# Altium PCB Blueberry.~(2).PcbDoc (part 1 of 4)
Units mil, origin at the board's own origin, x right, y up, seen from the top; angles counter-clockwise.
Board outline 2559.06 x 2204.72 mil, 6 copper layers (Top Layer, Mid-Layer 1, Mid-Layer 2, Mid-Layer 3, Mid-Layer 4, Bottom Layer); 211 components, 214 nets, 1171 pads, 598 vias.
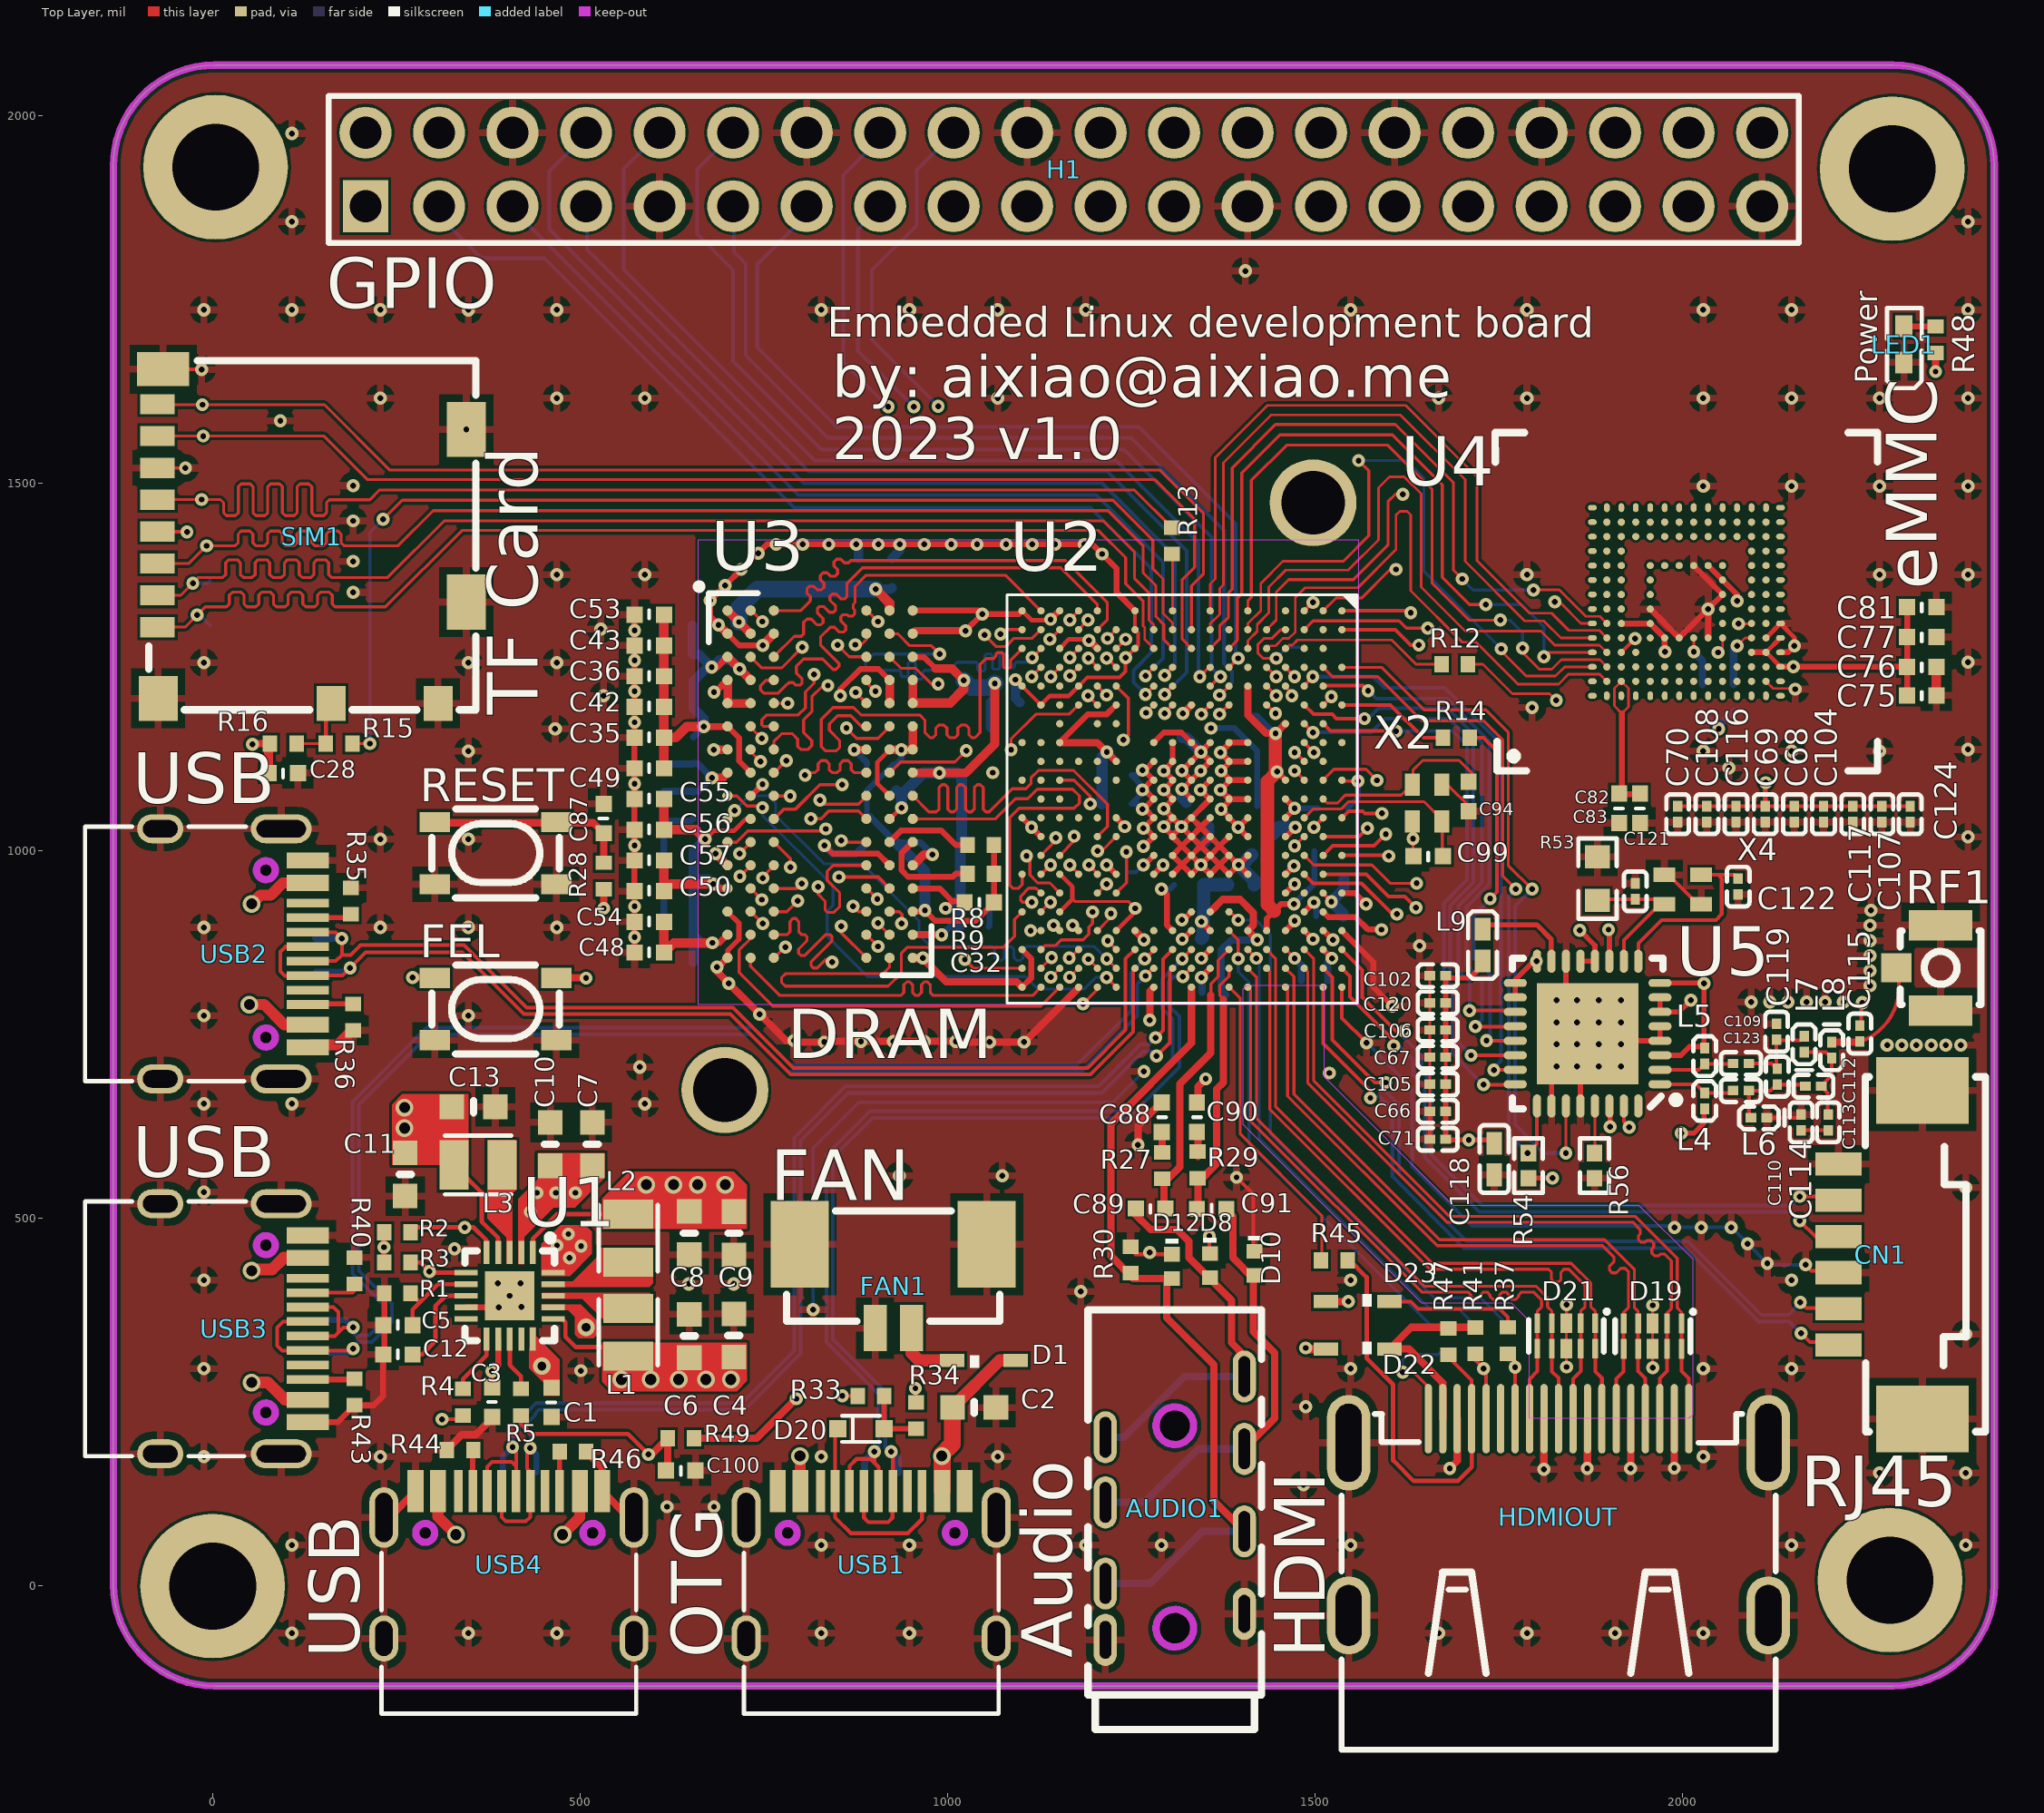
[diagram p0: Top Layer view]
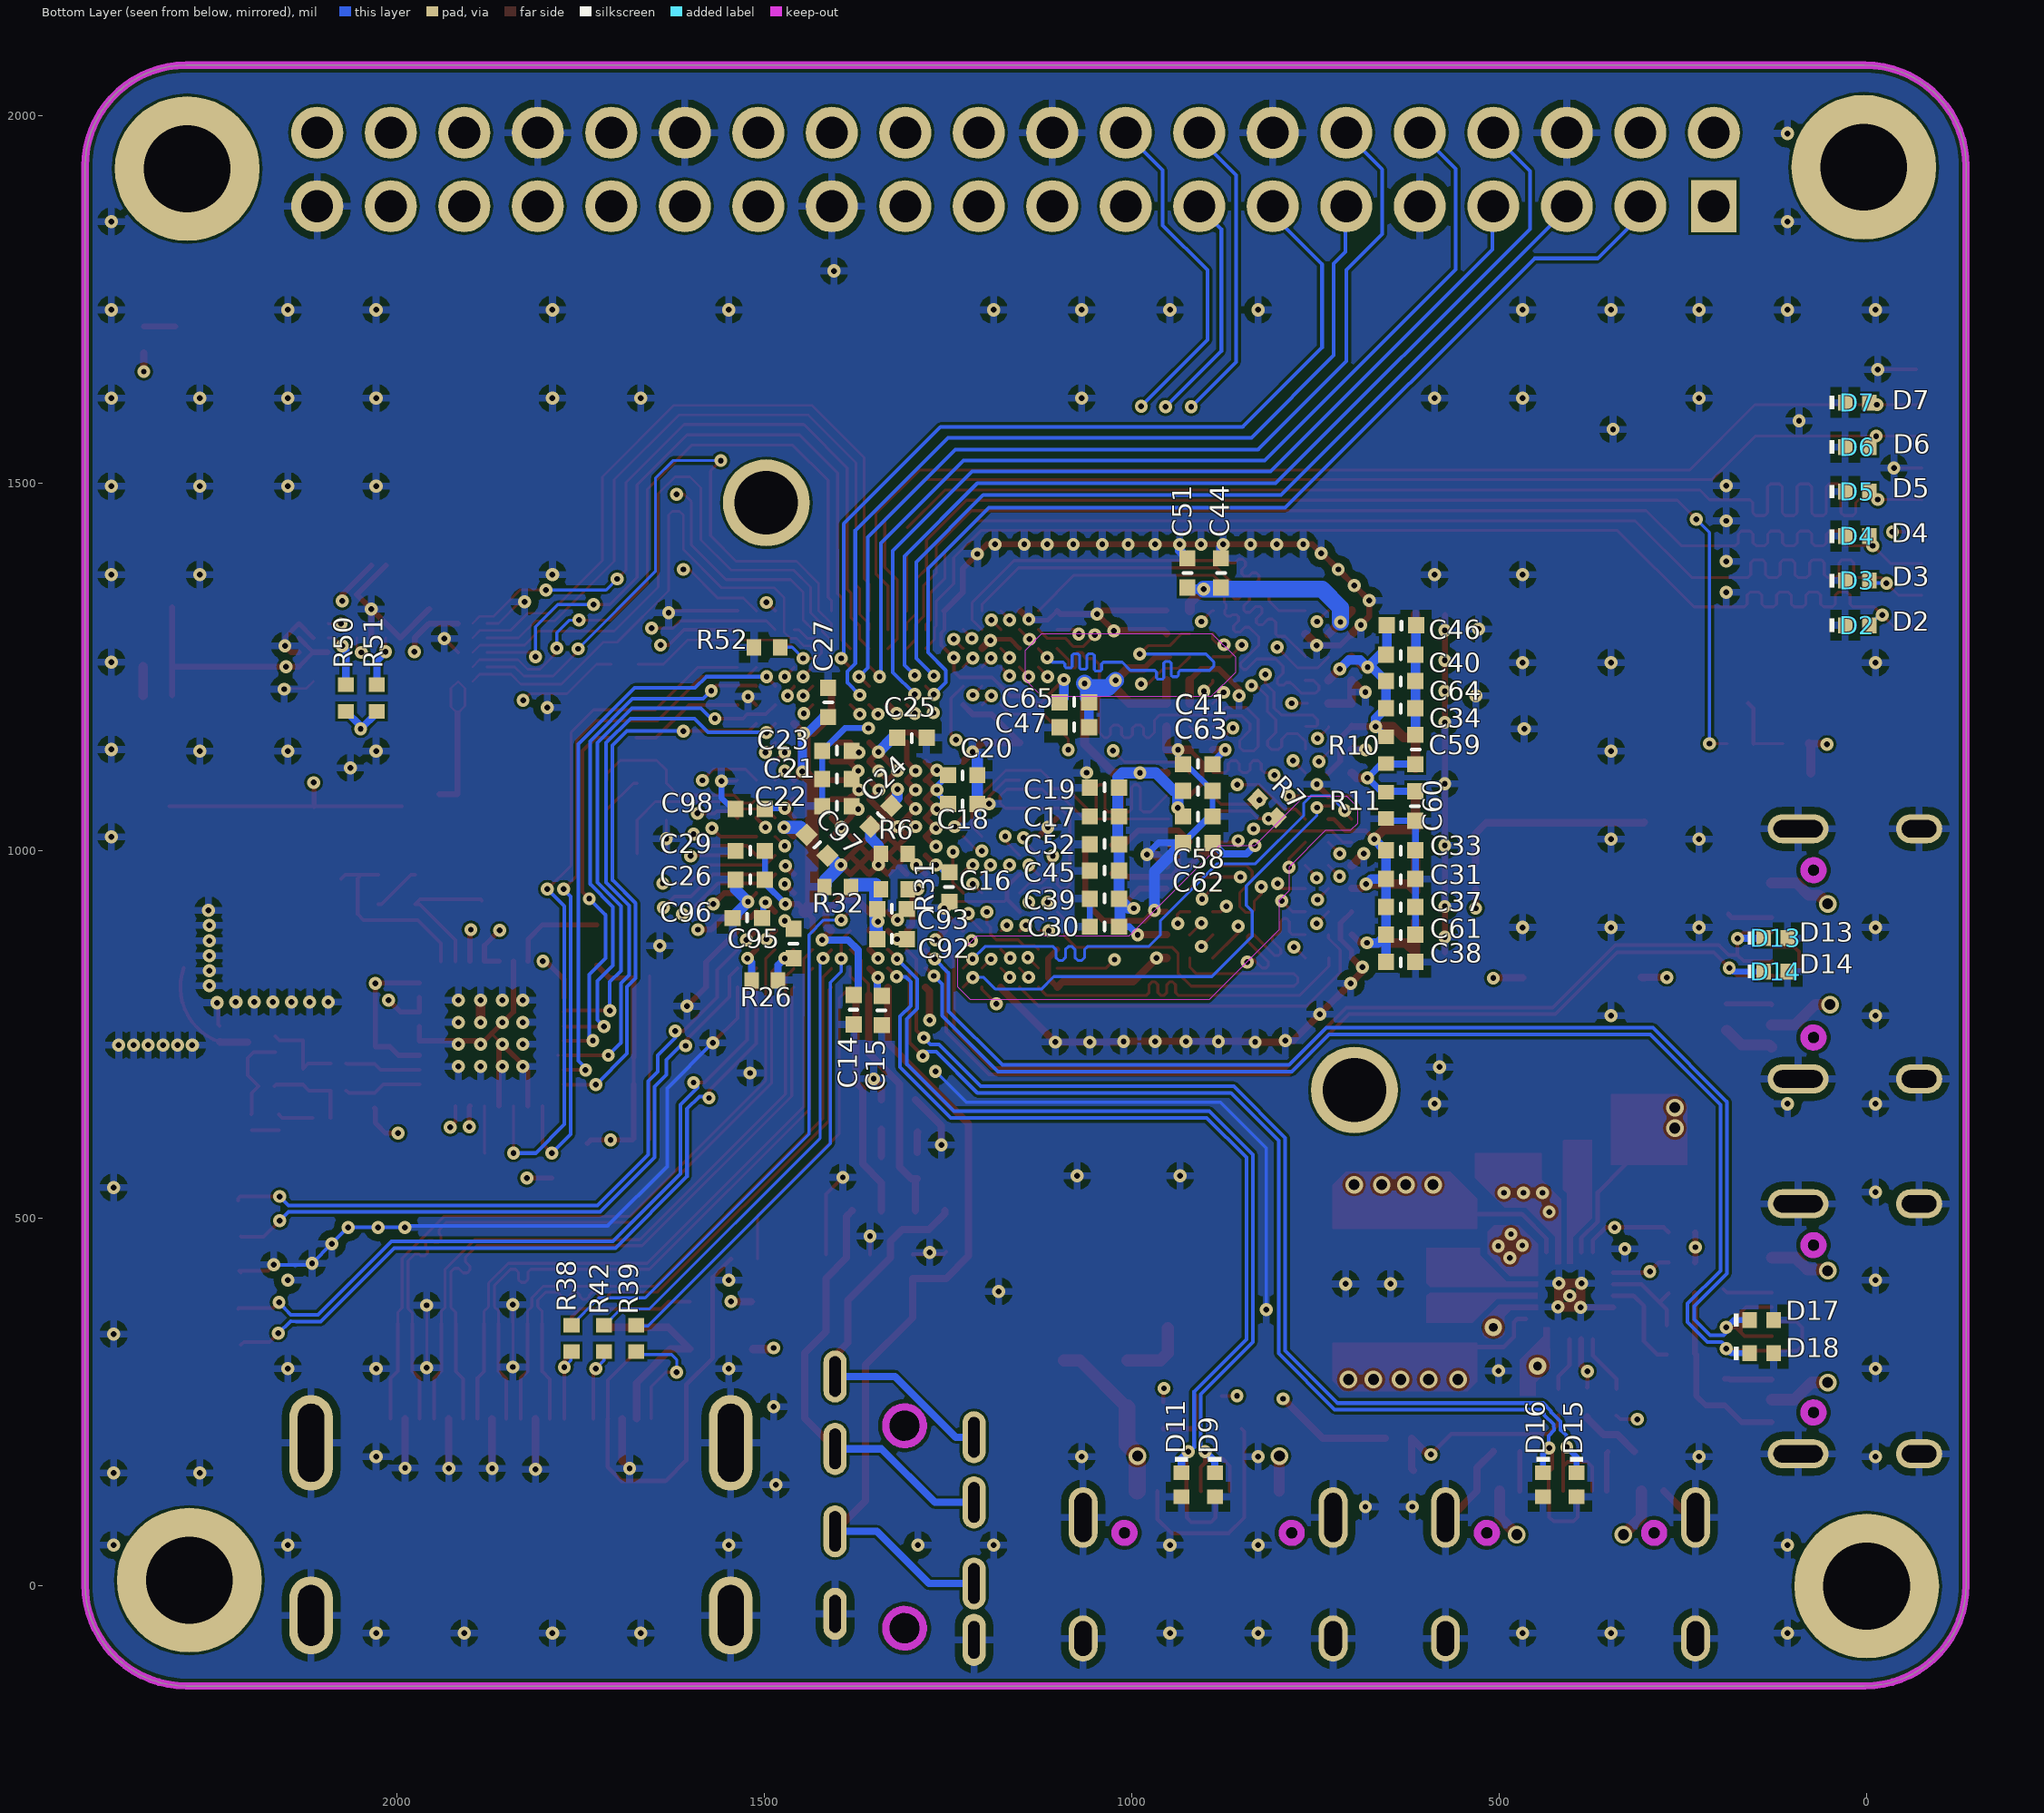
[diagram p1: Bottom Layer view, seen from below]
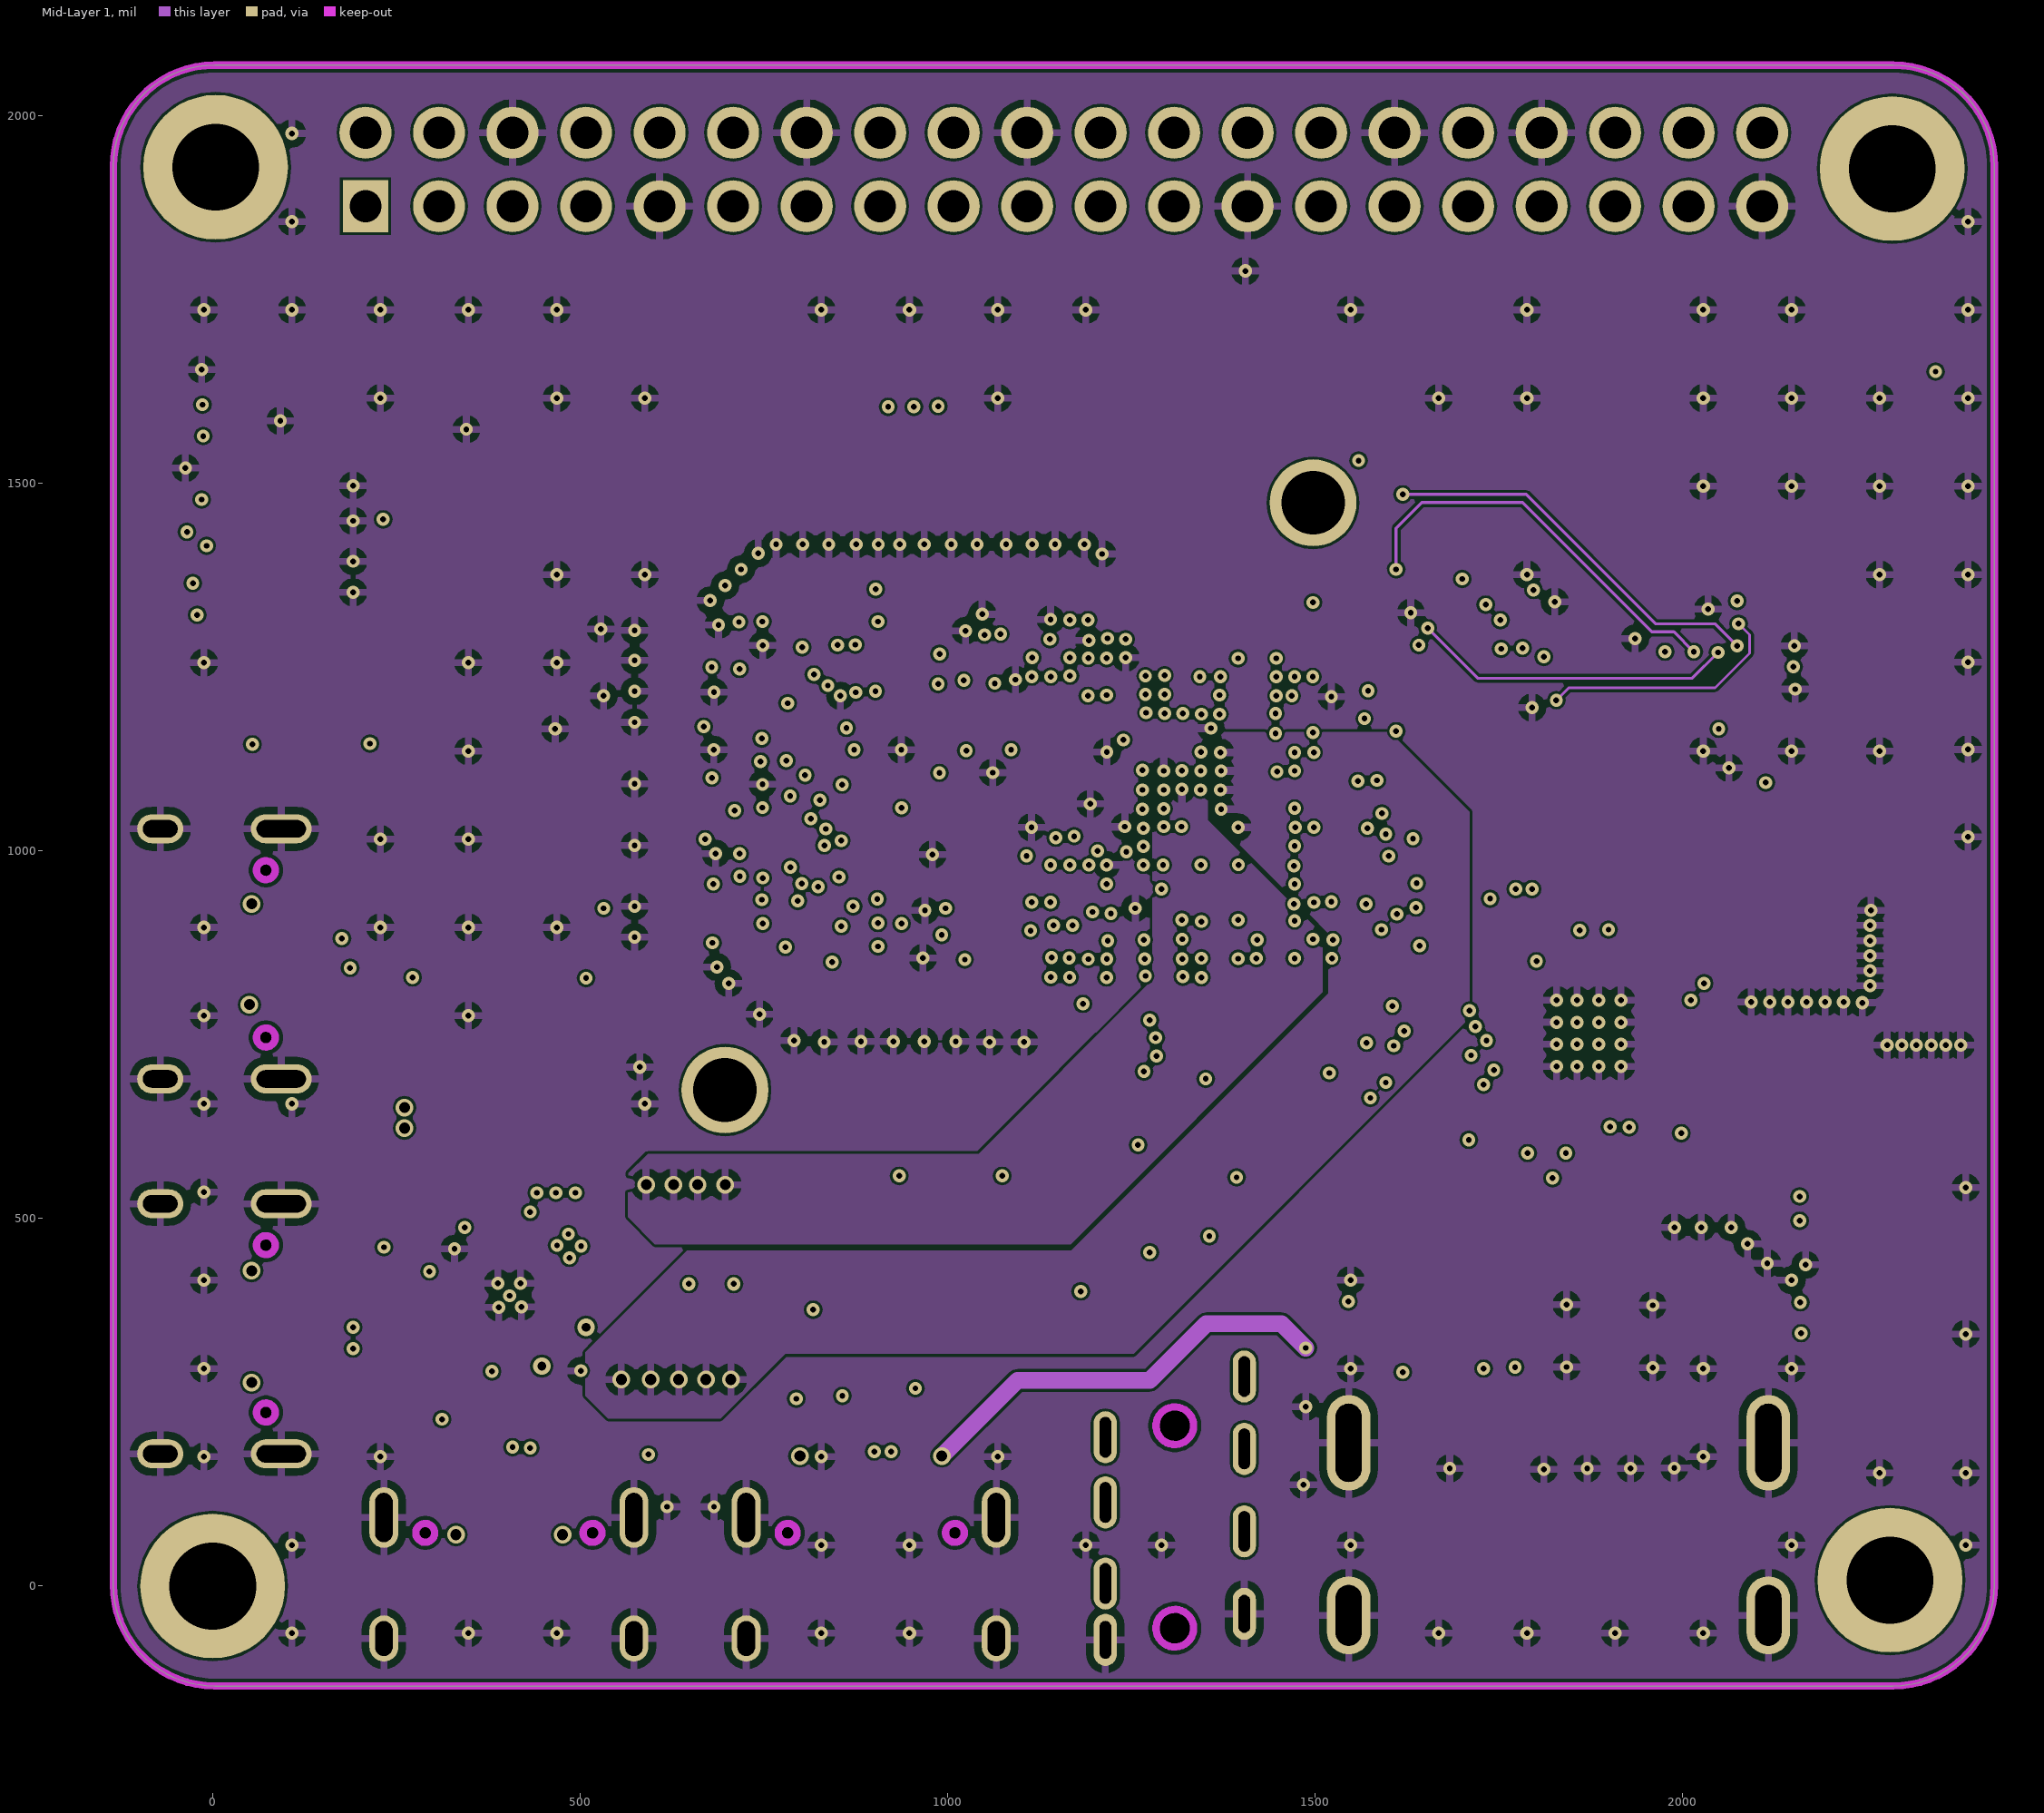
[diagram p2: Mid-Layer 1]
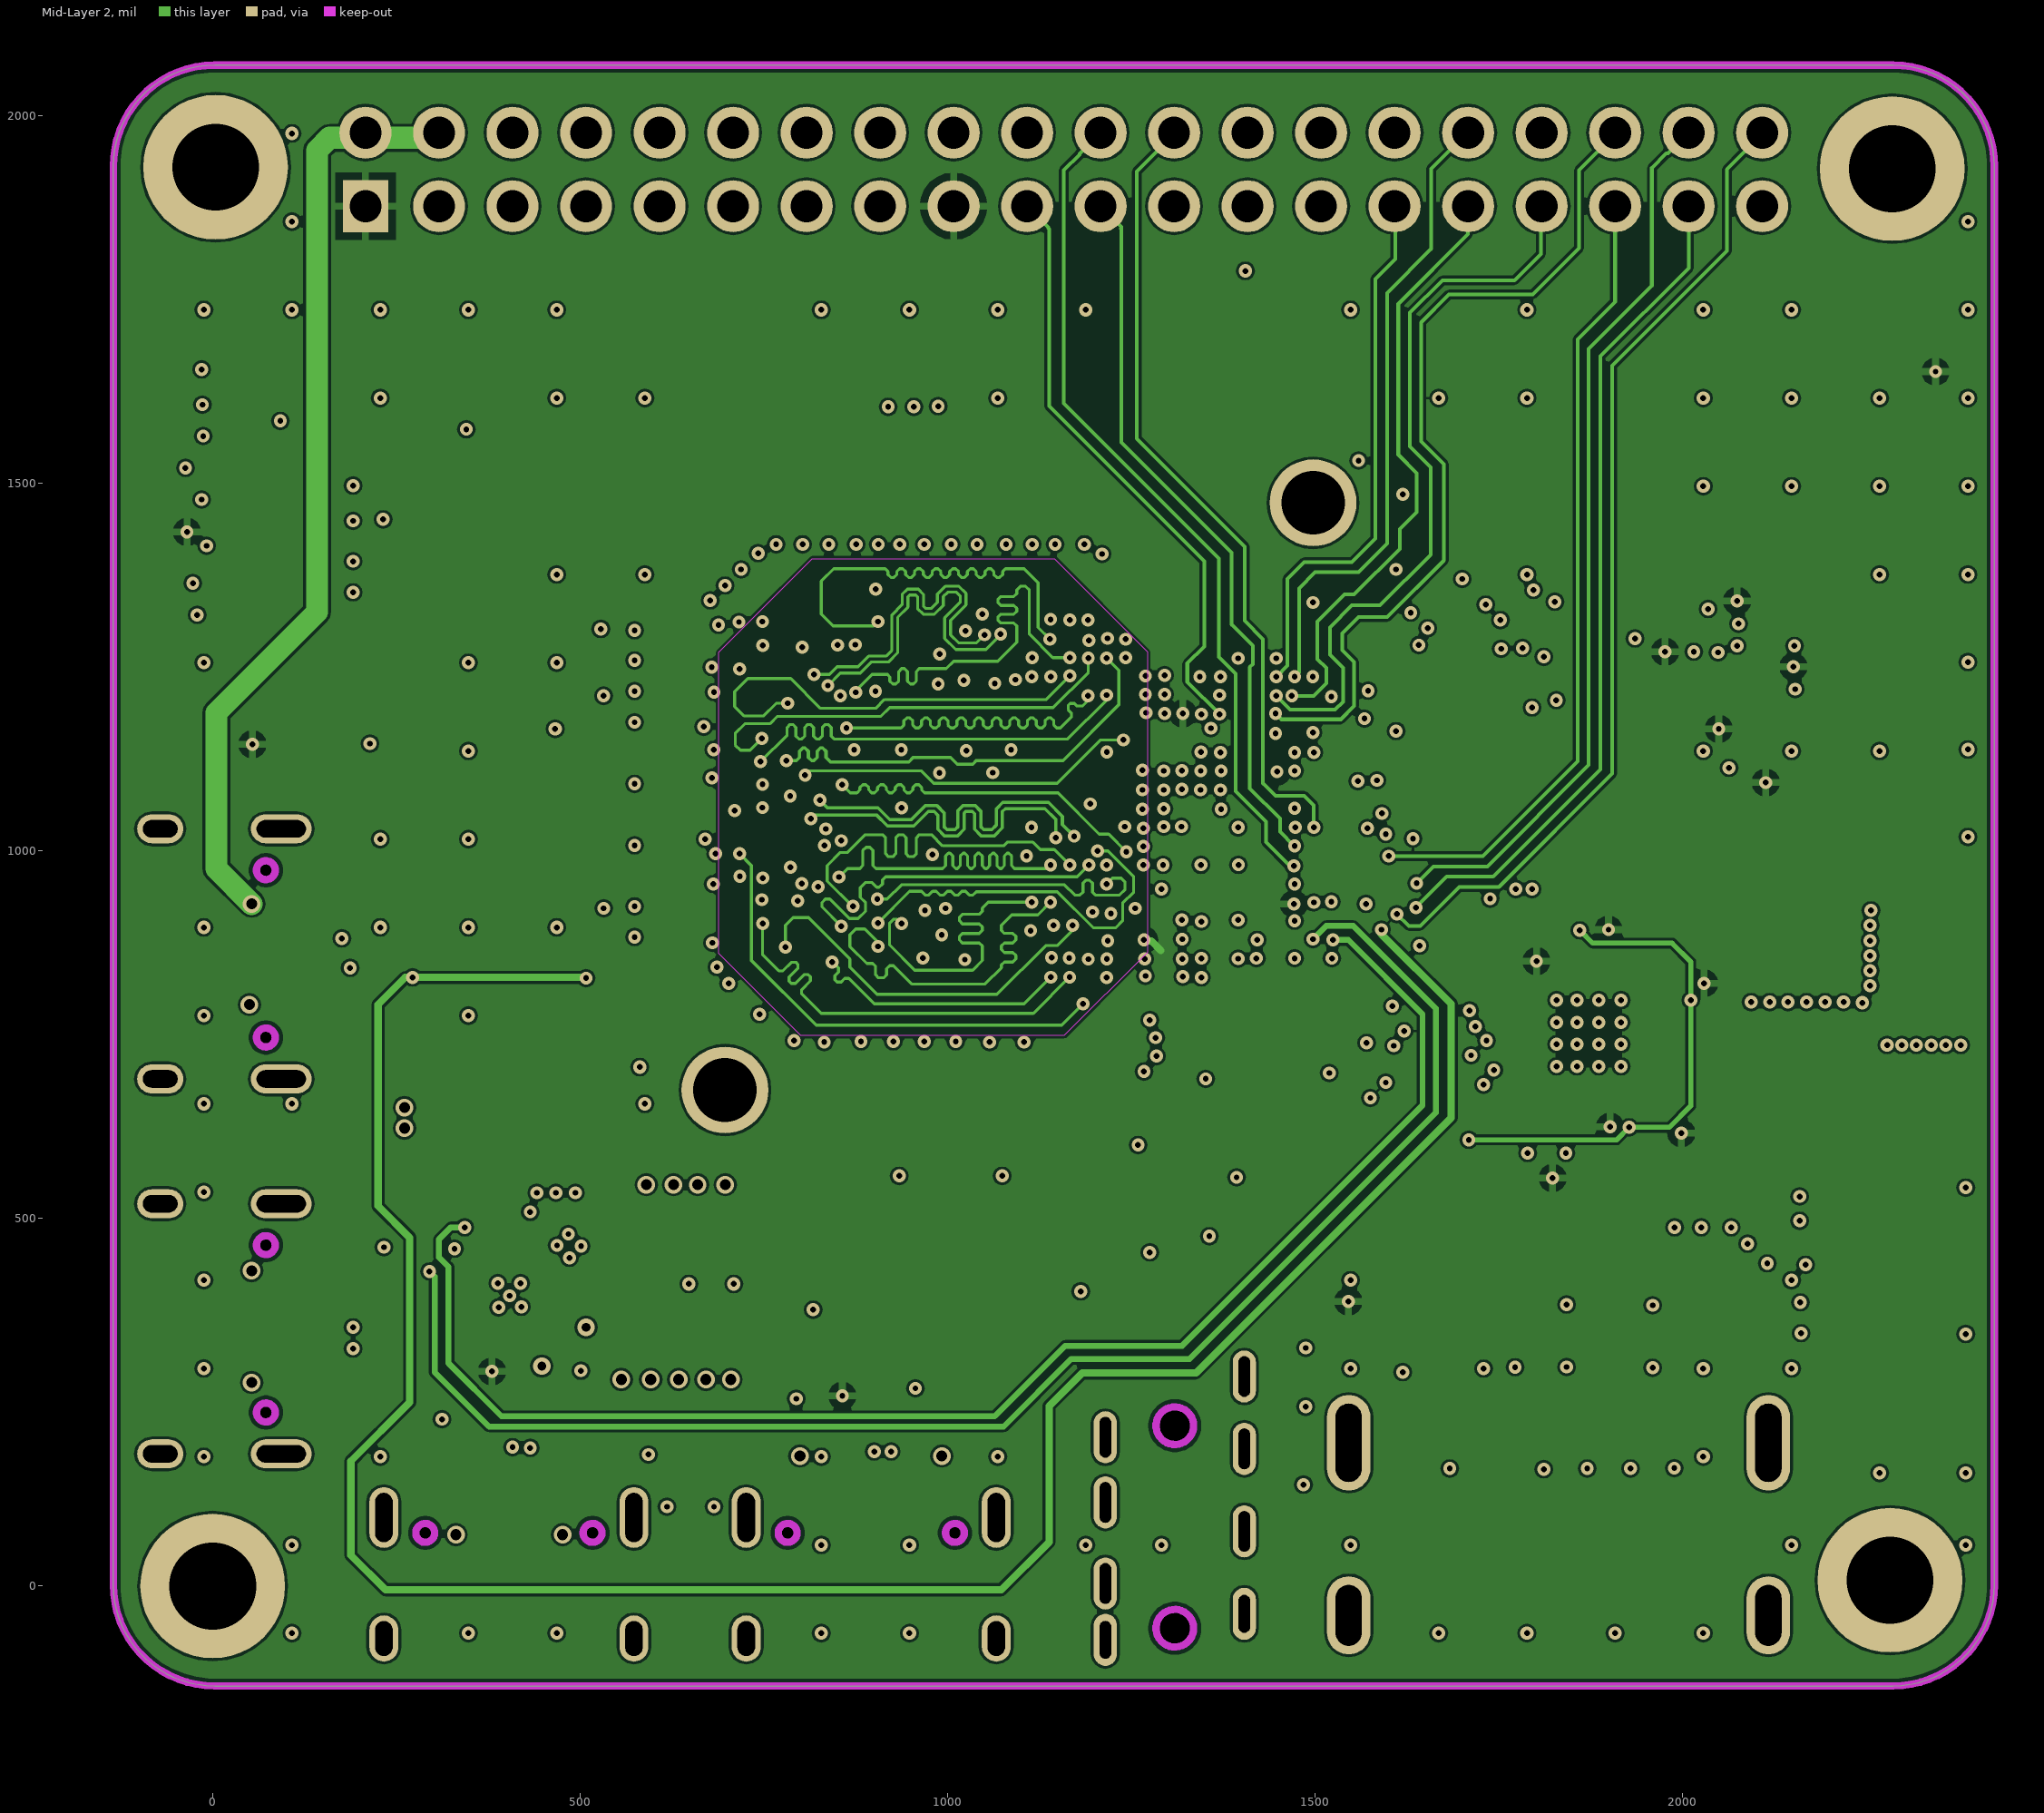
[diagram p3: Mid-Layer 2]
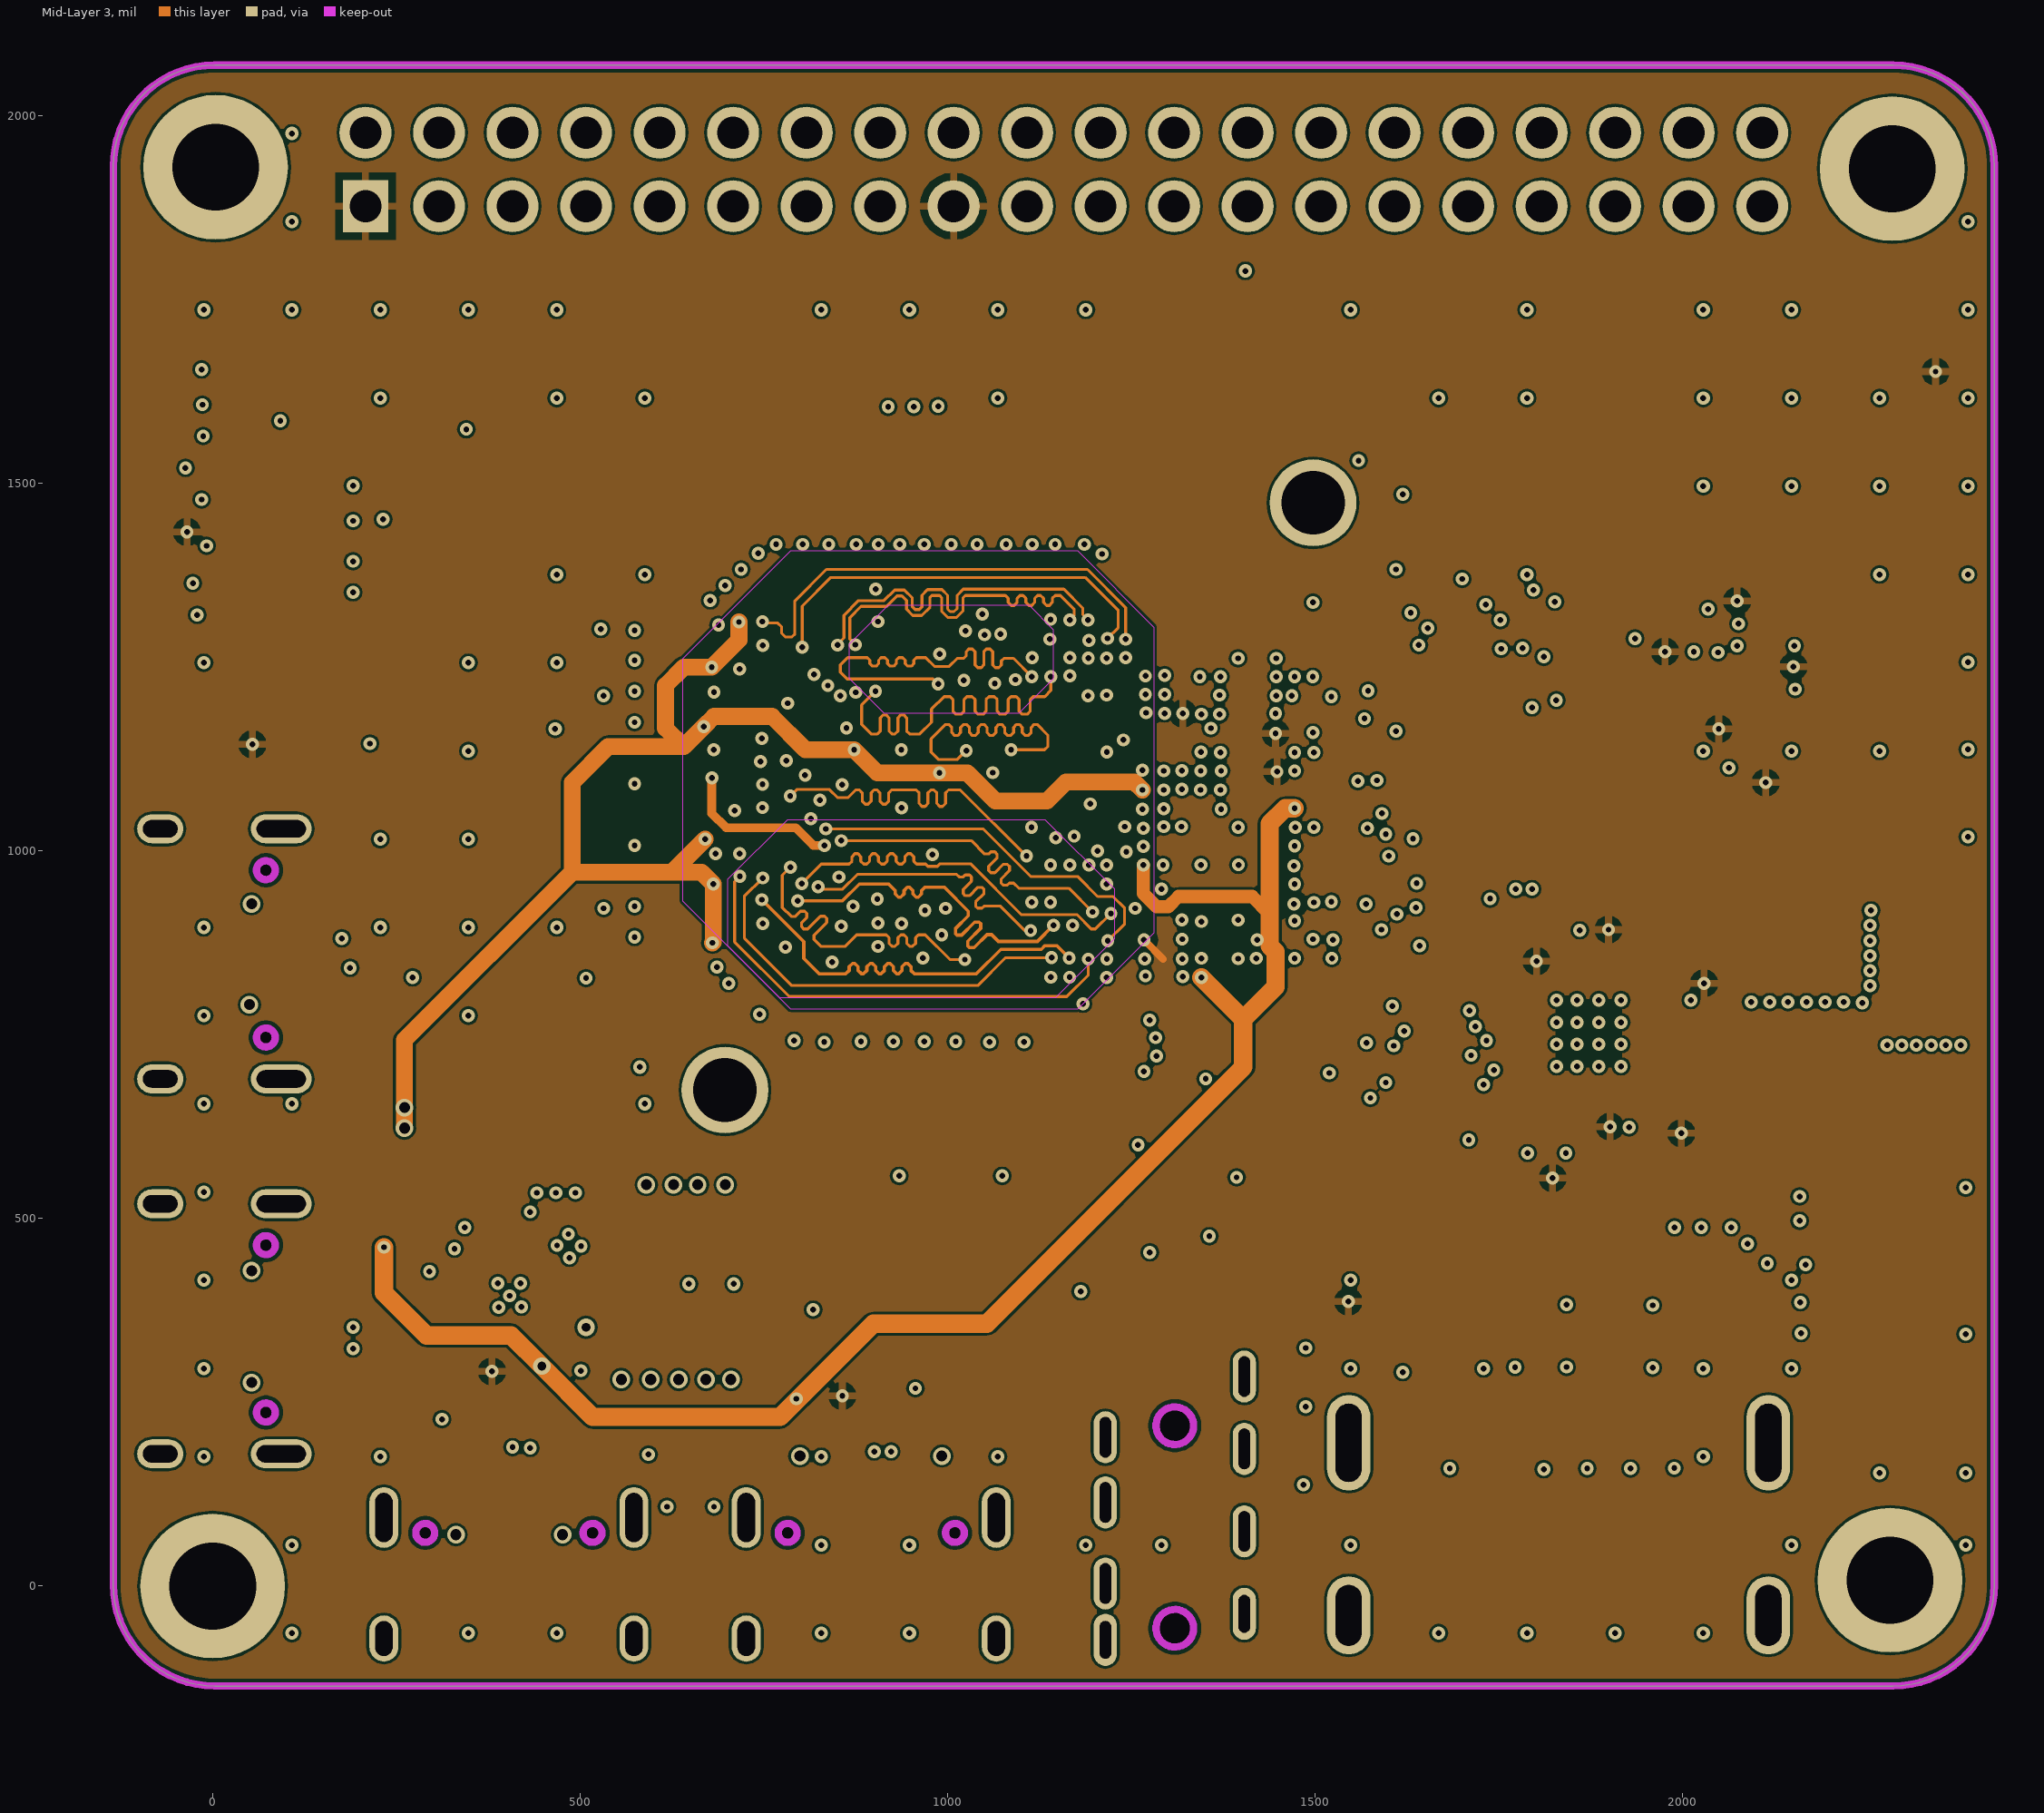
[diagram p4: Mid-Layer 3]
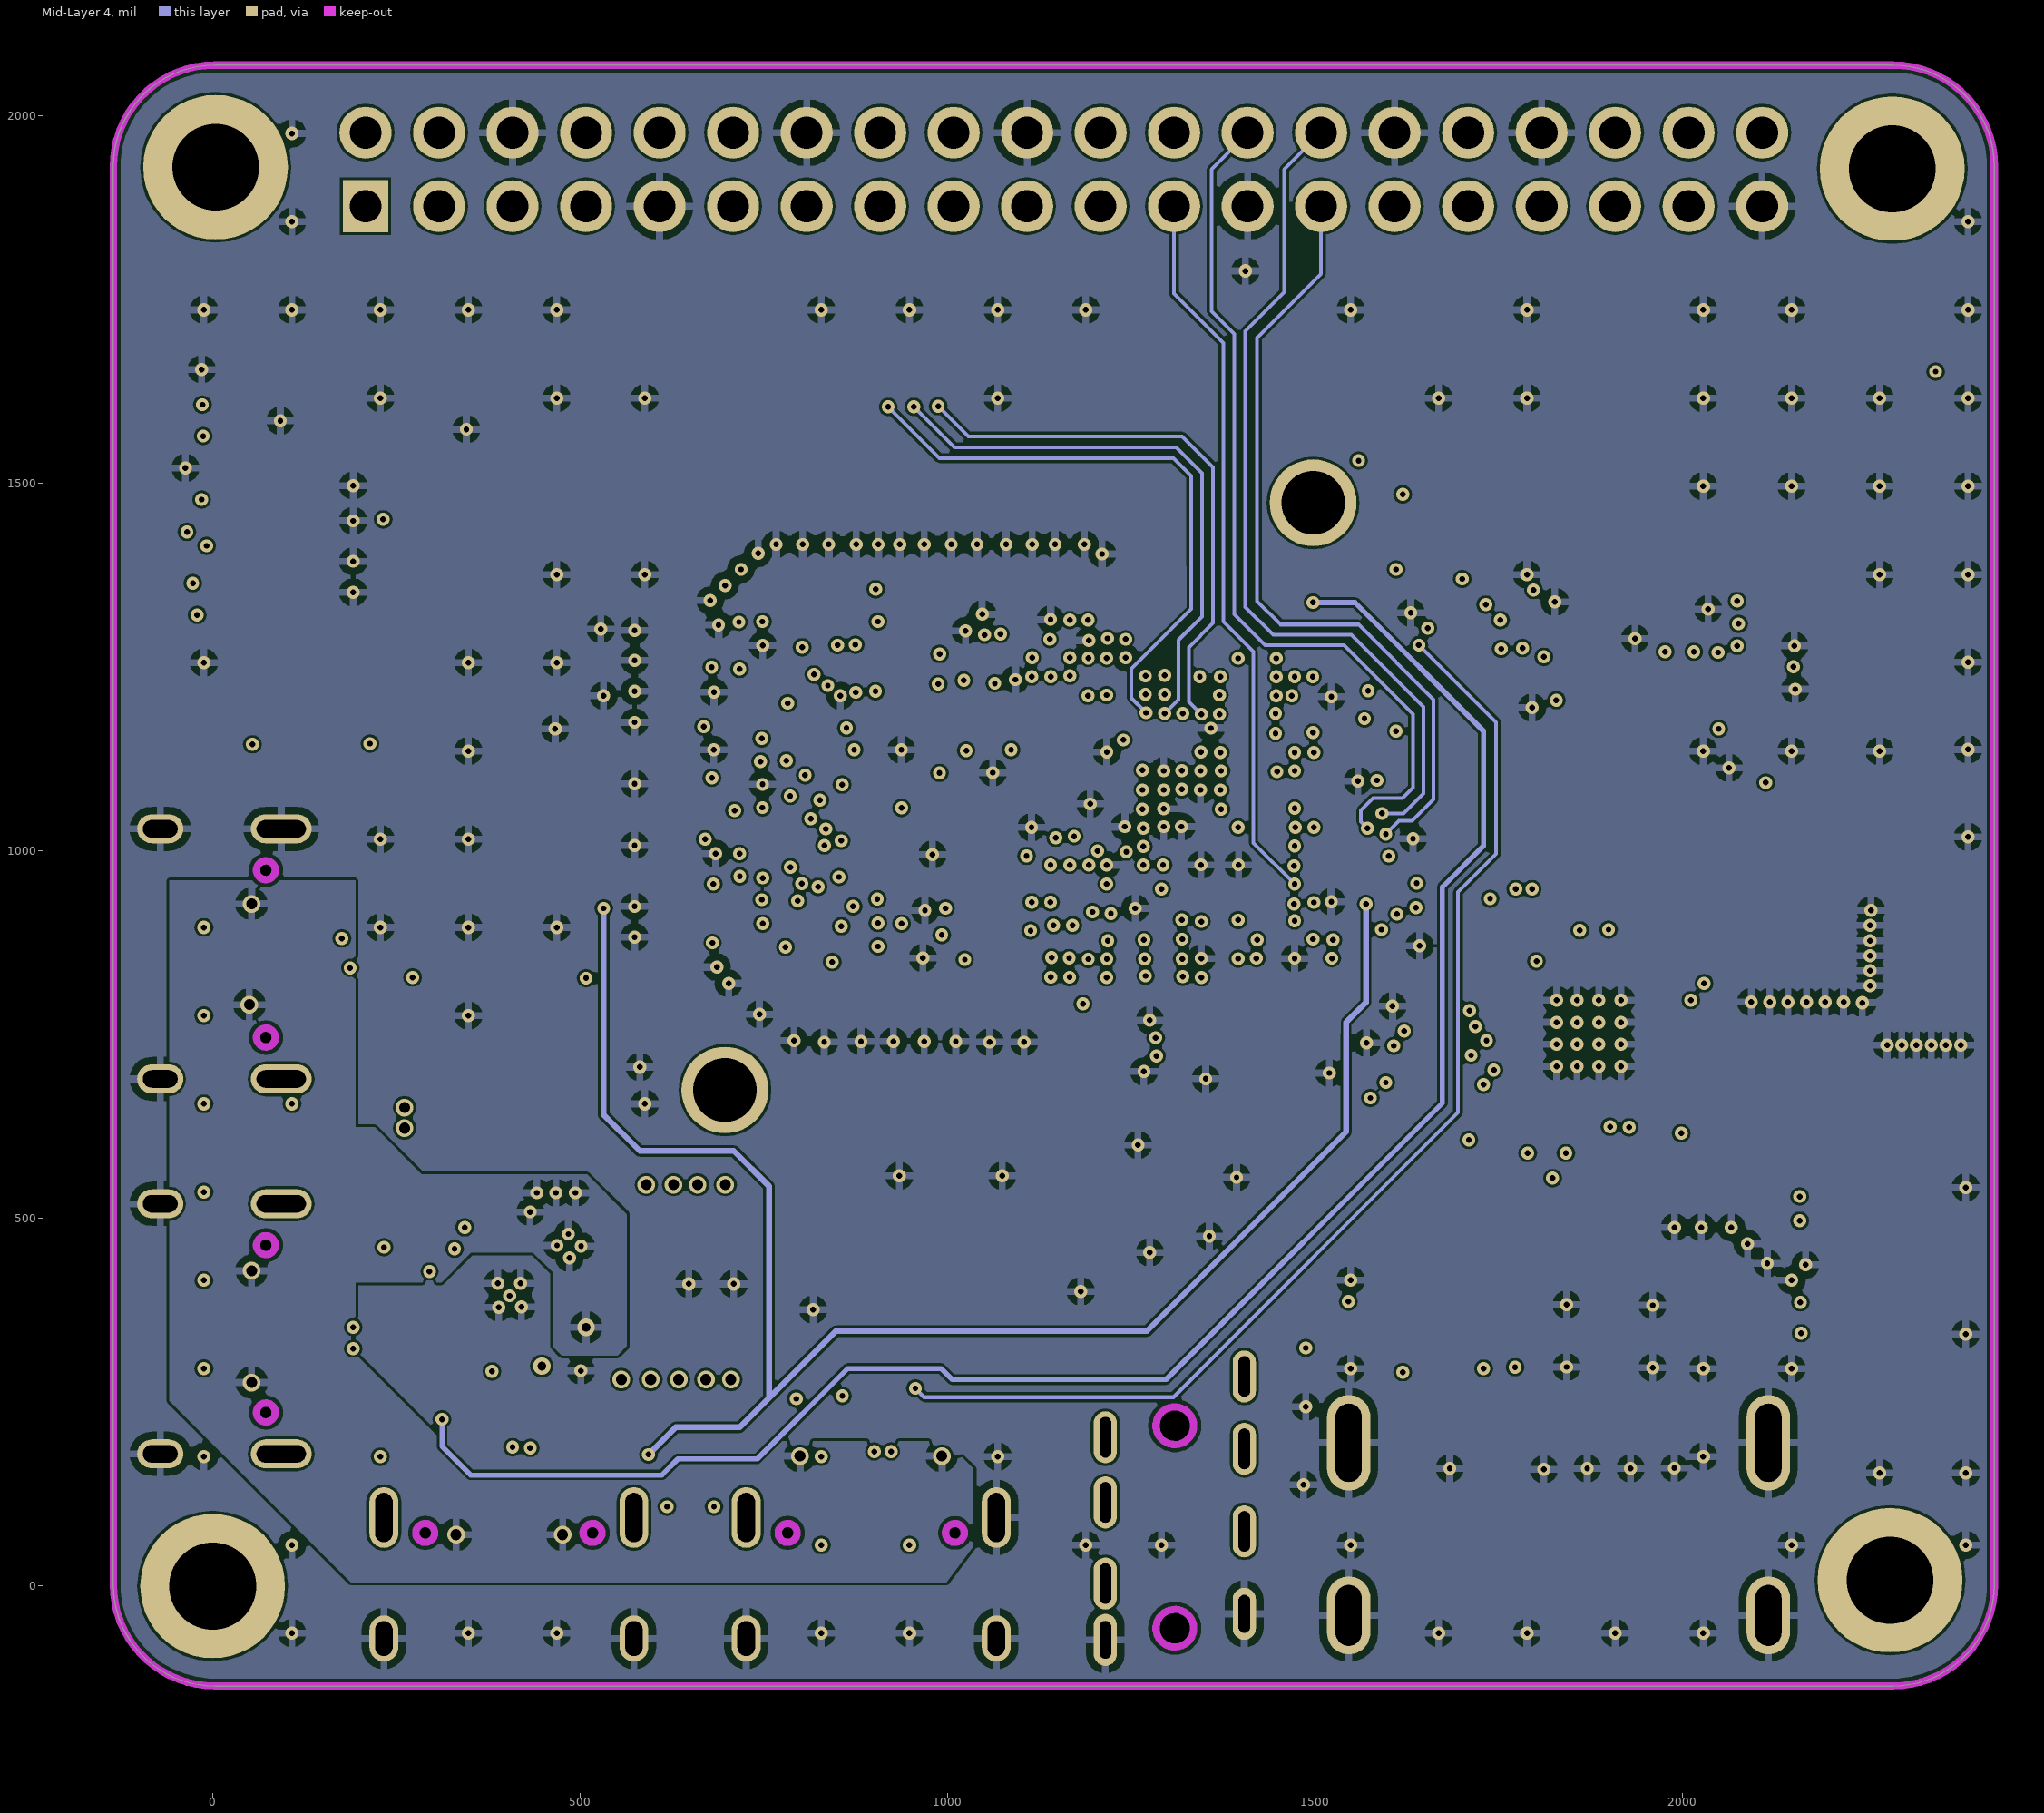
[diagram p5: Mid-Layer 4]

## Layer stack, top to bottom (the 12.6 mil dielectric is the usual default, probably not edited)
Top Solder: solder mask 0.4, Solder Resist, Dk 3.5
Top Layer: signal copper 1.4
Dielectric 1: dielectric 12.6, FR-4, Dk 4.8
Mid-Layer 1: signal copper 1.4
Dielectric4: dielectric 12.6, FR-4, Dk 4.8
Mid-Layer 2: signal copper 1.4
Dielectric3: dielectric 12.6, FR-4, Dk 4.8
Mid-Layer 3: signal copper 1.4
Dielectric2: dielectric 12.6, FR-4, Dk 4.8
Mid-Layer 4: signal copper 1.4
Dielectric5: dielectric 12.6, FR-4, Dk 4.8
Bottom Layer: signal copper 1.4
Bottom Solder: solder mask 0.4, Solder Resist, Dk 3.5

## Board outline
-135.17,1.96 ccw(c2.63,1.96) 2.63,-135.83 2286.09,-135.83 ccw(c2286.09,1.96) 2423.89,1.96 2423.89,1931.09 ccw(c2286.09,1931.09) 2286.09,2068.89 2.63,2068.89 ccw(c2.63,1931.09) -135.17,1931.09

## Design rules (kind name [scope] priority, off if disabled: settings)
BoardOutlineClearance [All] p1: gap=10 ignorepadtopadclearanceinfootprint=FALSE except(0: Arc-SplitContinuation Track-OutlineEdge Track-SplitContinuation SMDPad-SplitContinuation THPad-SplitContinuation Via-SplitContinuation Fill-SplitContinuation Poly-SplitContinuation Region-SplitContinuation Text-OutlineEdge Text-SplitContinuation; 3.5: Track-CutoutEdge SMDPad-OutlineEdge SMDPad-CutoutEdge THPad-OutlineEdge THPad-CutoutEdge Via-CutoutEdge Fill-CutoutEdge Region-CutoutEdge)
Clearance Via [All vs inpolygon] p1: gap=3.5 ignorepadtopadclearanceinfootprint=FALSE
Clearance [All] p2: gap=3.5 ignorepadtopadclearanceinfootprint=FALSE except(3: Arc-Arc; 7: Arc-Track Arc-SMDPad Arc-THPad Arc-Via Arc-Fill Arc-Poly Arc-Region Arc-Text Arc-Hole)
DiffPairsRouting [All] p1: maxlimit=10 minlimit=10 mostfreqgap=10 toplayer_minwidth=15 toplayer_maxwidth=15 toplayer_prefwidth=15 midlayer1_minwidth=15 midlayer1_maxwidth=15 midlayer1_prefwidth=15 midlayer2_minwidth=15 midlayer2_maxwidth=15 midlayer2_prefwidth=15 midlayer3_minwidth=15 midlayer3_maxwidth=15 midlayer3_prefwidth=15 midlayer4_minwidth=15 midlayer4_maxwidth=15 midlayer4_prefwidth=15 bottomlayer_minwidth=15 bottomlayer_maxwidth=15 bottomlayer_prefwidth=15 maxuncoupledlength=500
HoleSize [All] p1: absolutevalues=TRUE maxlimit=150 minlimit=1 maxpercent=80.000 minpercent=20.000
HoleToHoleClearance [All] p1: gap=0 allowstackedmicrovias=TRUE
MinimumSolderMaskSliver [All] p1: minsoldermaskwidth=0
PolygonConnect DRAMCopper [All] p1: connectstyle=Relief reliefconductorwidth=10 reliefentries=4 polygonreliefangle="90 Angle" airgapwidth=10
PolygonConnect TBCopper [All] p2: connectstyle=Relief reliefconductorwidth=4 reliefentries=4 polygonreliefangle="90 Angle" airgapwidth=4
PolygonConnect [All] p3: connectstyle=Relief reliefconductorwidth=10 reliefentries=4 polygonreliefangle="90 Angle" airgapwidth=10
RoutingVias [All] p1: holewidth=7.9 width=17.7 viastyle="Through Hole" minholewidth=7.9 minwidth=17.7 maxholewidth=28 maxwidth=50
SilkToSilkClearance [All] p1: silktosilkclearance=0
SilkToSolderMaskClearance [IsPad] p1: minsilkscreentomaskgap=0 clearancetoexposedcopper=TRUE
SolderMaskExpansion [All] p1: expansion=4 istentingtop=FALSE
SupplyNets "Schematic Supply Nets_7" [InNet('H5V')] p1: voltage=0.000
SupplyNets "Schematic Supply Nets_6" [InNet('VDD_CPU')] p2: voltage=0.000
SupplyNets "Schematic Supply Nets_5" [InNet('VCC_DRAM')] p3: voltage=0.000
SupplyNets "Schematic Supply Nets_4" [InNet('VDD_GPU')] p4: voltage=0.000
SupplyNets "Schematic Supply Nets_3" [InNet('VDD33')] p5: voltage=0.000
SupplyNets "Schematic Supply Nets_2" [InNet('GND')] p6: voltage=0.000
SupplyNets "Schematic Supply Nets_1" [InNet('1V8')] p7: voltage=0.000
SupplyNets "Schematic Supply Nets" [InNet('VBUS')] p8: voltage=0.000
Width [All] p1: maxlimit=100 minlimit=3 preferedwidth=4
24 further rules are at their usual default settings.

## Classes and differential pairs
component class POWER: C1 C2 C3 C4 C5 C6 C7 C8 C9 C10 C11 C12 C13 C14 C15 C16 C17 C18 C19 C20 C21 C22 C23 C24 C25 C26 C27 C28 C29 C100 D1 FAN1 L1 L2 L3 LED1 R1 R2 R3 R4 R5 R48 R49 U1
component class PLL-IO: AUDIO1 C87 C88 C89 C90 C91 C92 C93 C94 C95 C96 C97 C98 C99 CN1 D8 D9 D10 D11 D12 D13 D14 D15 D16 D17 D18 D19 D20 D21 D22 D23 FEL HDMIOUT R26 R27 R28 R29 R30 R31 R32 R33 R34 R35 R36 R37 R38 R39 R40 R41 R42 R43 R44 R45 R46 R47 RESET USB1 USB2 USB3 USB4 X2
component class IO: C66 C67 C68 C69 C70 C71 C75 C76 C77 C81 C82 C83 C102 C104 C105 C106 C107 C108 C109 C110 C112 C113 C114 C115 C116 C117 C118 C119 C120 C121 C122 C123 C124 D2 D3 D4 D5 D6 D7 H1 L4 L5 L6 L7 L8 L9 R12 R13 R14 R15 R16 R50 R51 R52 R53 R54 R56 RF1 SIM1 U4 U5 X4
component class DRAM: C30 C31 C32 C33 C34 C35 C36 C37 C38 C39 C40 C41 C42 C43 C44 C45 C46 C47 C48 C49 C50 C51 C52 C53 C54 C55 C56 C57 C58 C59 C60 C61 C62 C63 C64 C65 R6 R7 R8 R9 R10 R11 U2 U3
differential pair SDQS0: +SDQS0_P -SDQS0_N
differential pair EPHY_RX: +EPHY_RX_P -EPHY_RX_N
differential pair EPHY_TX: +EPHY_TX_P -EPHY_TX_N
differential pair D0: +D0_P -D0_N
differential pair D3: +D3_P -D3_N
differential pair D2: +D2_P -D2_N
differential pair HDMI_2: +HDMI_2_P -HDMI_2_N
differential pair HDMI_1: +HDMI_1_P -HDMI_1_N
differential pair HDMI_0: +HDMI_0_P -HDMI_0_N
differential pair HDMI_C: +HDMI_C_P -HDMI_C_N
differential pair D1: +D1_P -D1_N
differential pair SCK: +SCK_P -SCK_N
differential pair SDQS1: +SDQS1_P -SDQS1_N

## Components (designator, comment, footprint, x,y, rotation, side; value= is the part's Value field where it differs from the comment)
AUDIO1 "PJ-3930-8A" AUDIO-TH_PJ-3930-8A 1309,106 r180 top
C1 "CAP_0402" C0402-NSK 461,250 r90 top value=4.7uf
C2 "CAP_0603" "C0603 NSK" 1036,243 r0 top value=4.7uf
C3 "CAP_0402" C0402-NSK 380.44,250.27 r90 top value=4.7uf
C4 "CAP_0603" "C0603 NSK" 709.12,340.92 r90 top value=22uf
C5 "CAP_0402" C0402-NSK 252,355 r0 top value=4.7uf
C6 "CAP_0603" "C0603 NSK" 648.44,340.27 r90 top value=22uf
C7 "CAP_0603" "C0603 NSK" 516.44,601.27 r90 top value=4.7uf
C8 "CAP_0603" "C0603 NSK" 648.44,480.27 r270 top value=22uf
C9 "CAP_0603" "C0603 NSK" 709.12,479.92 r270 top value=22uf
C10 "CAP_0603" "C0603 NSK" 459.44,601.27 r90 top value=4.7uf
C11 "CAP_0603" "C0603 NSK" 262,560 r270 top value=22uf
C12 "CAP_0402" C0402-NSK 252,315 r0 top value=1uf
C13 "CAP_0603" "C0603 NSK" 355,652 r0 top value=22uf
C14 "CAP_0402" C0402-NSK 1378,784 r90 bottom value=100nF
C15 "CAP_0402" C0402-NSK 1340,783 r90 bottom value=100nF
C16 "CAP_0402" C0402-NSK 1248,951 r90 bottom value=100nF
C17 "CAP_0402" C0402-NSK 1036.97,1047.01 r180 bottom value=100nF
C18 "CAP_0402" C0402-NSK 1229.97,1064.01 r0 bottom value=100nF
C19 "CAP_0402" C0402-NSK 1037.03,1085.96 r180 bottom value=100nF
C20 "CAP_0402" C0402-NSK 1229.97,1103.01 r0 bottom value=100nF
C21 "CAP_0402" C0402-NSK 1401,1098 r180 bottom value=100nF
C22 "CAP_0402" C0402-NSK 1401,1061 r180 bottom value=100nF
C23 "CAP_0402" C0402-NSK 1401,1136 r180 bottom value=100nF
C24 "CAP_0402" C0402-NSK 1341,1047 r135 bottom value=100nF
C25 "CAP_0402" C0402-NSK 1299,1154 r0 bottom value=100nF
C26 "CAP_0402" C0402-NSK 1519,961 r180 bottom value=100nF
C27 "CAP_0402" C0402-NSK 1413,1202 r270 bottom value=100nF
C28 "CAP_0402" C0402-NSK 96.01,1106 r180 top value=100nF
C29 "CAP_0402" C0402-NSK 1519,1000 r180 bottom value=100nF
C30 "CAP_0402" C0402-NSK 1037,897 r180 bottom value=100nF
C31 "CAP_0402" C0402-NSK 634,962 r0 bottom value=100nF
C32 "CAP_0402" C0402-NSK 1043,930 r180 top value=100nF
C33 "CAP_0402" C0402-NSK 634,1001 r0 bottom value=100nF
C34 "CAP_0402" C0402-NSK 634,1194 r0 bottom value=100nF
C35 "CAP_0402" C0402-NSK 594,1154.15 r0 top value=100nF
C36 "CAP_0402" C0402-NSK 594,1237.69 r0 top value=100nF
C37 "CAP_0402" C0402-NSK 634,924 r0 bottom value=100nF
C38 "CAP_0402" C0402-NSK 634,849 r0 bottom value=100nF
C39 "CAP_0402" C0402-NSK 1037,935 r180 bottom value=100nF
C40 "CAP_0402" C0402-NSK 633.99,1267 r0 bottom value=100nF
C41 "CAP_0402" C0402-NSK 910,1118 r180 bottom value=100nF
C42 "CAP_0402" C0402-NSK 594,1195.92 r0 top value=100nF
C43 "CAP_0402" C0402-NSK 594,1279.46 r0 top value=100nF
C44 "CAP_0402" C0402-NSK 878.58,1378.16 r270 bottom value=100nF
C45 "CAP_0402" C0402-NSK 1037,973 r180 bottom value=100nF
C46 "CAP_0402" C0402-NSK 632.99,1307 r0 bottom value=100nF
C47 "CAP_0402" C0402-NSK 1078,1168 r180 bottom value=100nF
C48 "CAP_0402" C0402-NSK 594,861.77 r0 top value=100nF
C49 "CAP_0402" C0402-NSK 594,1112.38 r0 top value=100nF
C50 "CAP_0402" C0402-NSK 594,945.31 r0 top value=100nF
C51 "CAP_0402" C0402-NSK 924.27,1378.16 r270 bottom value=100nF
C52 "CAP_0402" C0402-NSK 1037,1009 r180 bottom value=100nF
C53 "CAP_0402" C0402-NSK 594,1321.23 r0 top value=100nF
C54 "CAP_0402" C0402-NSK 594,903.54 r0 top value=100nF
C55 "CAP_0402" C0402-NSK 594,1070.62 r0 top value=100nF
C56 "CAP_0402" C0402-NSK 594,1028.85 r0 top value=100nF
C57 "CAP_0402" C0402-NSK 594,987.08 r0 top value=100nF
C58 "CAP_0402" C0402-NSK 910,1011 r180 bottom value=100nF
C59 "CAP_0402" C0402-NSK 614,1138 r270 bottom value=100nF
C60 "CAP_0402" C0402-NSK 614,1061 r90 bottom value=100nF
C61 "CAP_0402" C0402-NSK 633.99,886 r0 bottom value=100nF
C62 "CAP_0402" C0402-NSK 910,1047 r0 bottom value=100nF
C63 "CAP_0402" C0402-NSK 910,1082 r0 bottom value=100nF
C64 "CAP_0402" C0402-NSK 634,1231 r0 bottom value=100nF
C65 "CAP_0402" C0402-NSK 1078,1202 r180 bottom value=100nF
C66 "CL03A104KO3NNNC" C0201 1666.65,645.8 r180 top value=100nF
C67 "CL03A104KO3NNNC" C0201 1666.65,719.6 r180 top value=100nF
C68 "CL03A104KO3NNNC" C0201 2151.89,1050 r90 top value=100nF
C69 "CL03A104KO3NNNC" C0201 2112.19,1050 r90 top value=100nF
C70 "CL03A104KO3NNNC" C0201 1993.08,1050 r90 top value=100nF
C71 "CL03A104KO3NNNC" C0201 1666.65,607.9 r0 top value=100nF
C75 "CAP_0402" C0402-NSK 2325.16,1211.58 r180 top value=2.2uF
C76 "CAP_0402" C0402-NSK 2325.16,1250.27 r180 top value=2.2uF
C77 "CAP_0402" C0402-NSK 2325.16,1290.95 r180 top value=2.2uF
C81 "CAP_0402" C0402-NSK 2325.16,1331.64 r180 top value=2.2uF
C82 "CAP_0402" C0402-NSK 1913.46,1058 r90 top value=2.2uF
C83 "CAP_0402" C0402-NSK 1941.87,1058 r90 top value=2.2uF
C87 "FN15X104K250PNG" C0402-NSK 532,1044 r90 top value=100nF
C88 "CAP_0402" C0402-NSK 1291,637.75 r270 top value=100nF
C89 "CAP_0402" C0402-NSK 1276,513.63 r180 top value=4.7uF
C90 "CAP_0402" C0402-NSK 1339,637.75 r270 top value=100nF
C91 "CAP_0402" C0402-NSK 1358.99,513 r0 top value=4.7uF
C92 "CAP_0402" C0402-NSK 1326.16,880 r180 bottom value=470nF
C93 "CAP_0402" C0402-NSK 1326.16,921 r180 bottom value=470nF
C94 "CAP_0402" C0402-NSK 1708.63,1074 r270 top value=22pf
C95 "CAP_0402" C0402-NSK 1459.94,874 r90 bottom value=2.2uF
C96 "CAP_0402" C0402-NSK 1523,908.79 r180 bottom value=1uF
C97 "CAP_0402" C0402-NSK 1428,1008 r225 bottom value=220nF
C98 "CAP_0402" C0402-NSK 1518.99,1057 r0 bottom value=100nf
C99 "CAP_0402" C0402-NSK 1653.72,993 r180 top value=22pf
C100 "CAP_0402" C0402-NSK 636.81,157.36 r180 top value=100nF
C102 "0201CG101J500NT" C0201 1666.65,830.31 r0 top value=100pF
C104 "CL03A104KO3NNNC" C0201 2191.6,1050 r270 top value=100nF
C105 "CL03A104KO3NNNC" C0201 1666.65,682.7 r180 top value=100nF
C106 "CL03A104KO3NNNC" C0201 1666.65,756.5 r180 top value=100nF
C107 "CL03A104KO3NNNC" C0201 2271,1050 r90 top value=100nF
C108 "CL03A104KO3NNNC" C0201 2032.78,1050 r270 top value=100nF
C109 "0201CG7R0C250NT" C0201 2079.21,711 r180 top value=7pF
C110 "GRM0335C1H1R0WA01D" C0201 2128.65,693 r270 top value=1pF
C112 "0201CG1R2B500NT" C0201 2177.83,680 r0 top value=1.2pF
C113 "GRM0335C1H1R0WA01D" C0201 2198,630.82 r90 top value=1pF
C114 "GRM0335C1H1R0WA01D" C0201 2161,630.82 r270 top value=1pF
C115 "GRM0335C1H1R0WA01D" C0201 2241,751.54 r270 top value=1pF
C116 "GRM035R60J475ME15D" C0201 2072.49,1050 r90 top value=4.7uF
C117 "CL03A104KO3NNNC" C0201 2231.3,1050 r90 top value=100nF
C118 "CL05A106MQ5NUNC" C0402 1743.47,580.84 r90 top value=10uF
C119 "0201CG1R2B500NT" C0201 2127.65,754 r90 top value=1.2pF
C120 "CL03A104KO3NNNC" C0201 1666.65,793.4 r180 top value=100nF
C121 "CC0201JRNPO9BN220" C0201 1935.42,945.09 r90 top value=22pF
C122 "CC0201JRNPO9BN220" C0201 2075.43,951.45 r270 top value=22pF
C123 "0201CG7R0C250NT" C0201 2079.21,674 r180 top value=7pF
C124 "GRM035R60J475ME15D" C0201 2309.53,1050 r270 top value=4.7uF
CN1 "532610671" CONN-SMD_6P-P1.25_53261-0671 2268.98,451 r90 top
D1 "B5819WS" SOD-323_L1.8-W1.3-LS2.5-NSK 1049,307 r0 top
D2 "0402ESDA-05N" D0402 12.79,1307 r180 bottom
D3 "0402ESDA-05N" D0402 12.79,1367.6 r180 bottom
D4 "0402ESDA-05N" D0402 12.79,1428.2 r180 bottom
D5 "0402ESDA-05N" D0402 12.79,1488.8 r180 bottom
D6 "0402ESDA-05N" D0402 12.79,1549.4 r180 bottom
D7 "0402ESDA-05N" D0402 12.79,1610 r180 bottom
D8 "0402ESDA-05N" D0402 1356.73,436 r270 top
D9 "0402ESDA-05N" D0402 886.86,137.97 r270 bottom
D10 "0402ESDA-05N" D0402 1417.56,439 r270 top
D11 "0402ESDA-05N" D0402 932.23,137.97 r270 bottom
D12 "0402ESDA-05N" D0402 1305,435 r270 top
D13 "0402ESDA-05N" D0402 123.99,881.47 r180 bottom
D14 "0402ESDA-05N" D0402 123.99,836.1 r180 bottom
D15 "0402ESDA-05N" D0402 394.86,137.97 r270 bottom
D16 "0402ESDA-05N" D0402 440.23,137.97 r270 bottom
D17 "0402ESDA-05N" D0402 142.99,361.99 r180 bottom
D18 "0402ESDA-05N" D0402 142.99,316.62 r180 bottom
D19 "RClamp0524PATCT" SLP2510P8_L2.5-W1.0-P0.50-BL 1959,340 r180 top
D20 "1N5819-SOD523" SOD-523_L1.2-W0.8-LS1.6-FD 882,214 r180 top
D21 "RClamp0524PATCT" SLP2510P8_L2.5-W1.0-P0.50-BL 1841.6,340.3 r180 top
D22 "B5819WS" SOD-323_L1.8-W1.3-LS2.5-NSK 1558,322.5 r180 top
D23 "B5819WS" SOD-323_L1.8-W1.3-LS2.5-NSK 1558,387 r180 top
FAN1 "0533980271" CONN-SMD_2P-P1.25_053398-0X71 926,408 r180 top
FEL "PTS810SJM250SMTRLFS" KEY-SMD_4P-L4.2-W3.2-P2.20-LS4.6 385,785 r0 top
H1 "B-2100S40P-B110" HDR-TH_40P-P2.54-V-M-R2-C20-S2.54 1158,1927 r0 top
HDMIOUT "HDMI-019S" HDMI-SMD_HDMI-019S 1831,94 r0 top
L1 "CKCS201610-2.2uH/M_2" IND-SMD_L2.0-W1.6_1 565.44,345.27 r90 top value=1uH
L2 "CKCS201610-2.2uH/M_2" IND-SMD_L2.0-W1.6_1 565.44,473.27 r270 top value=1uH
L3 "CKCS201610-2.2uH/M_2" IND-SMD_L2.0-W1.6_1 361.12,572.92 r0 top value=1uH
L4 "LQP03TN10NH02D" L0201 2029.84,660 r270 top value=10nH
L5 "LQP03TN10NH02D" L0201 2029.84,721.03 r90 top value=10nH
L6 "SDCL0603Q2N7BT02B03" L0201-RD 2103.62,637 r180 top value=2.7nH
L7 "SDCL0603Q2N7BT02B03" L0201-RD 2165.16,737 r90 top value=2.7nH
L8 "SDCL0603Q2N7BT02B03" L0201-RD 2202.65,729.05 r270 top value=2.7nH
L9 "MLZ1005N4R7LTD25" L0402 1727.73,872 r90 top value=4.7uH
LED1 "XL-1005SURC" LED0402-R-RD_RED 2301,1689 r90 top
R1 "Res_0402" R0402-NSK_2 251.44,398.27 r0 top value=510
R2 "Res_0402" R0402-NSK_2 251.44,481.27 r0 top value=2k
R3 "Res_0402" R0402-NSK_2 251.44,440.27 r0 top value=2k
R4 "Res_0402" R0402-NSK_2 340.44,250.27 r90 top value=0
R5 "Res_0402" R0402-NSK_2 419.44,250.27 r90 top value=0
R6 "Res_0402" R0402-NSK_2 1323,996 r0 bottom value=240
R7 "Res_0402" R0402-NSK_2 816,1058 r225 bottom value=100
R8 "Res_0402" R0402-NSK_2 1045,1008 r180 top value=240
R9 "Res_0402" R0402-NSK_2 1045,969 r180 top value=240
R10 "Res_0402" R0402-NSK_2 654,1137 r90 bottom value=2k
R11 "Res_0402" R0402-NSK_2 654,1062 r90 bottom value=2k
R12 "Res_0402" R0402-NSK_2 1690,1254 r180 top value=33
R13 "Res_0402" R0402-NSK_2 1305,1422 r270 top value=33
R14 "Res_0402" R0402-NSK_2 1692,1154.01 r180 top value=33
R15 "Res_0402" R0402-NSK_2 172,1146 r180 top value=1K
R16 "Res_0402" R0402-NSK_2 96,1146 r0 top value=47K
R26 "Res_0402" R0402-NSK_2 1499,824 r180 bottom value=6.04k
R27 "Res_0402" R0402-NSK_2 1291.57,572 r270 top value=22
R28 "TR0402D10K0Q1025Z" R0402-NSK_2 532,966 r90 top value=510
R29 "Res_0402" R0402-NSK_2 1340,572.93 r270 top value=22
R30 "Res_0402" R0402-NSK_2 1248.78,443.62 r270 top value=75
R31 "Res_0402" R0402-NSK_2 1323,948 r180 bottom value=150K
R32 "Res_0402" R0402-NSK_2 1400,951.01 r180 bottom value=0
R33 "Res_0402" R0402-NSK_2 895.64,258.71 r180 top value=47k
R34 "Res_0402" R0402-NSK_2 957,232 r270 top value=1K
R35 "Res_0402" R0402-NSK_2 188,932 r270 top value=5.1k
R36 "Res_0402" R0402-NSK_2 191,774 r270 top value=5.1k
R37 "Res_0402" R0402-NSK_2 1761.99,334 r270 top value=27K
R38 "Res_0402" R0402-NSK_2 1761.99,337 r270 bottom value=100
R39 "Res_0402" R0402-NSK_2 1674,337 r270 bottom value=1k
R40 "Res_0402" R0402-NSK_2 193,429 r270 top value=5.1k
R41 "Res_0402" R0402-NSK_2 1718,334 r270 top value=10K
R42 "Res_0402" R0402-NSK_2 1718,337 r270 bottom value=100
R43 "Res_0402" R0402-NSK_2 193,264 r270 top value=5.1k
R44 "Res_0402" R0402-NSK_2 336.68,185 r0 top value=5.1k
R45 "Res_0402" R0402-NSK_2 1525.99,443 r0 top value=100
R46 "Res_0402" R0402-NSK_2 490,183 r0 top value=5.1k
R47 "Res_0402" R0402-NSK_2 1681,332.56 r270 top value=10K
R48 "Res_0402" R0402-NSK_2 2344,1695.45 r270 top value=5.1k
R49 "Res_0402" R0402-NSK_2 637,201 r0 top value=10K
R50 "Res_0402" R0402-NSK_2 2069,1208 r90 bottom value=47K
R51 "Res_0402" R0402-NSK_2 2027,1208 r90 bottom value=47K
R52 "Res_0402" R0402-NSK_2 1496,1277 r0 bottom value=10k
R53 "0603WAF1004T5E" R0603 1884,962.42 r270 top value=1MΩ
R54 "RC0402FR-07100KL" R0402 1790.12,572 r270 top value=100kΩ
R56 "RC0402FR-0710KL" R0402 1880,572 r270 top value=10kΩ
RESET "PTS810SJM250SMTRLFS" KEY-SMD_4P-L4.2-W3.2-P2.20-LS4.6 385,997 r0 top
RF1 "BWIPX-1-001E" IPEX-SMD_BWIPX-1-001E 2320.73,841 r0 top
SIM1 "1040310811" SIM-SMD_8P-1040310811 135,1428 r270 top
U1 "AXP1530" WQFN-20_L3.0-W3.0-P0.40-BL-EP 404.12,394.92 r180 top
U2 "Allwinner_H616" BGA284P65B1200_1400H125 1318.77,1070.68 r270 top
U3 "H5TQ4G63EFR-RDC" FBGA96 828.77,1085.68 r0 top
U4 "EMMC BGA153" FBGA-153_L13.0-W11.5 2005,1339 r90 top
U5 "RTL8189ES-VB-CG" QFN-32_L5.0-W5.0-P0.50-TL-EP3.5 1870.65,751.54 r180 top
USB1 "TYPEC-304-BCP16" USB-C-SMD_TYPEC-304-BCP16-1 896,29 r0 top
USB2 "TYPEC-304-BCP16" USB-C-SMD_TYPEC-304-BCP16-1 29,860 r270 top
USB3 "TYPEC-304-BCP16" USB-C-SMD_TYPEC-304-BCP16-1 29,350 r270 top
USB4 "TYPEC-304-BCP16" USB-C-SMD_TYPEC-304-BCP16-1 403,29 r0 top
X2 "24M" OSC-SMD_4P-L2.0-W1.6-BL 1652.22,1065 r270 top value=-
X4 "40M" osc-smd_4p-l2.0-w1.6-bl 2000,947.54 r180 top value=-

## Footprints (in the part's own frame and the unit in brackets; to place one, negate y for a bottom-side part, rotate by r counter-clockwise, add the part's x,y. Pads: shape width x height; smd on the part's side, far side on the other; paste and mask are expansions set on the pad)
AUDIO-TH_PJ-3930-8A [mil]
  oval 31.5x70.9 hole 15.7 slot 51.2 at 90 deg paste-99999 mask+2: 1(-94.5,143.7) 8(94.5,179.1)
  oval 31.5x70.9 hole 15.7 slot 55.1 at 90 deg paste-99999 mask+2: 2(94.5,-96.5) 3(-94.5,-80.7) 4(-94.5,31.5) 5(-94.5,-179.1) 6(94.5,-7.9) 7(94.5,102.4)
  Keep-Out Layer board cut-out: -25.6,-112.2 -25.6,-115.57 -23.86,-122.08 -20.49,-127.92 -15.72,-132.69 -9.88,-136.06 -3.37,-137.8 3.37,-137.8 9.88,-136.06 15.72,-132.69 20.49,-127.92 23.86,-122.08 25.6,-115.57 25.6,-112.2 25.6,-108.83 23.86,-102.32 20.49,-96.48 15.72,-91.72 9.88,-88.34 3.37,-86.6 -3.37,-86.6 -9.88,-88.34 -15.72,-91.72 -20.49,-96.48 -23.86,-102.32 -25.6,-108.83 -25.6,-112.2
  Keep-Out Layer board cut-out: -25.6,163.3 -25.6,159.93 -23.86,153.42 -20.49,147.58 -15.72,142.81 -9.88,139.44 -3.37,137.7 3.37,137.7 9.88,139.44 15.72,142.81 20.49,147.58 23.86,153.42 25.6,159.93 25.6,163.3 25.6,166.67 23.86,173.18 20.49,179.02 15.72,183.78 9.88,187.16 3.37,188.9 -3.37,188.9 -9.88,187.16 -15.72,183.78 -20.49,179.02 -23.86,173.18 -25.6,166.67 -25.6,163.3
  Keep-Out Layer circle w10: c0,-112.2 r25.6
  Keep-Out Layer circle w0.2: c0,-112.2 r25.6
  Keep-Out Layer circle w10: c0,163.3 r25.6
  Keep-Out Layer circle w0.2: c0,163.3 r25.6
  silkscreen extent -118,-270 118,301, body extent -118,-276 118,303, height 215
BGA284P65B1200_1400H125 [mil]
  round 10 smd paste+0.98 mask+1.97: A1(-255.91,217.52) A2(-230.31,217.52) A4(-179.13,217.52) A6(-127.95,217.52) A8(-76.77,217.52) A10(-25.59,217.52) A12(25.59,217.52) A14(76.77,217.52) A16(127.95,217.52) A18(179.13,217.52) A19(204.72,217.52) A20(230.31,217.52) A21(255.91,217.52) B1(-255.91,191.93) B2(-230.31,191.93) B3(-204.72,191.93) B4(-179.13,191.93) B5(-153.54,191.93) B6(-127.95,191.93) B7(-102.36,191.93) B8(-76.77,191.93) B9(-51.18,191.93) B10(-25.59,191.93) B11(0,191.93) B12(25.59,191.93) B13(51.18,191.93) B14(76.77,191.93) B15(102.36,191.93) B16(127.95,191.93) B17(153.54,191.93) B18(179.13,191.93) B19(204.72,191.93) B20(230.31,191.93) B21(255.91,191.93) C1(-255.91,166.34) C2(-230.31,166.34) C3(-204.72,166.34) C4(-179.13,166.34) C5(-153.54,166.34) C6(-127.95,166.34) C7(-102.36,166.34) C8(-76.77,166.34) C9(-51.18,166.34) C10(-25.59,166.34) C11(0,166.34) C12(25.59,166.34) C13(51.18,166.34) C14(76.77,166.34) C15(102.36,166.34) C16(127.95,166.34) C17(153.54,166.34) C18(179.13,166.34) C19(204.72,166.34) C20(230.31,166.34) D1(-255.91,140.75) D2(-230.31,140.75) D3(-204.72,140.75) D4(-179.13,140.75) D5(-153.54,140.75) D7(-102.36,140.75) D10(-25.59,140.75) D11(0,140.75) D12(25.59,140.75) D13(51.18,140.75) D14(76.77,140.75) D15(102.36,140.75) D16(127.95,140.75) D18(179.13,140.75) D19(204.72,140.75) D20(230.31,140.75) D21(255.91,140.75) E2(-230.31,115.16) E3(-204.72,115.16) E4(-179.13,115.16) E5(-153.54,115.16) E6(-127.95,115.16) E18(179.13,115.16) E19(204.72,115.16) E20(230.31,115.16) F1(-255.91,89.57) F2(-230.31,89.57) F3(-204.72,89.57) F4(-179.13,89.57) F5(-153.54,89.57) F8(-76.77,89.57) F9(-51.18,89.57) F10(-25.59,89.57) F11(0,89.57) F12(25.59,89.57) F13(51.18,89.57) F14(76.77,89.57) F15(102.36,89.57) F18(179.13,89.57) F19(204.72,89.57) F20(230.31,89.57) F21(255.91,89.57) G2(-230.31,63.98) G3(-204.72,63.98) G4(-179.13,63.98) G5(-153.54,63.98) G6(-127.95,63.98) G8(-76.77,63.98) G9(-51.18,63.98) G10(-25.59,63.98) G11(0,63.98) G12(25.59,63.98) G13(51.18,63.98) G14(76.77,63.98) G15(102.36,63.98) G17(153.54,63.98) G18(179.13,63.98) G19(204.72,63.98) G20(230.31,63.98) G21(255.91,63.98) H1(-255.91,38.39) H2(-230.31,38.39) H3(-204.72,38.39) H4(-179.13,38.39) H5(-153.54,38.39) H6(-127.95,38.39) H8(-76.77,38.39) H9(-51.18,38.39) H10(-25.59,38.39) H11(0,38.39) H12(25.59,38.39) H13(51.18,38.39) H14(76.77,38.39) H15(102.36,38.39) H17(153.54,38.39) H18(179.13,38.39) H19(204.72,38.39) H20(230.31,38.39) J2(-230.31,12.8) J3(-204.72,12.8) J6(-127.95,12.8) J8(-76.77,12.8) J9(-51.18,12.8) J10(-25.59,12.8) J11(0,12.8) J12(25.59,12.8) J13(51.18,12.8) J14(76.77,12.8) J15(102.36,12.8) J17(153.54,12.8) J18(179.13,12.8) J19(204.72,12.8) J20(230.31,12.8) J21(255.91,12.8) K1(-255.91,-12.8) K2(-230.31,-12.8) K3(-204.72,-12.8) K4(-179.13,-12.8) K5(-153.54,-12.8) K6(-127.95,-12.8) K8(-76.77,-12.8) K9(-51.18,-12.8) K10(-25.59,-12.8) K11(0,-12.8) K12(25.59,-12.8) K13(51.18,-12.8) K14(76.77,-12.8) K15(102.36,-12.8) K18(179.13,-12.8) K19(204.72,-12.8) K20(230.31,-12.8) L2(-230.31,-38.39) L3(-204.72,-38.39) L4(-179.13,-38.39) L5(-153.54,-38.39) L6(-127.95,-38.39) L8(-76.77,-38.39) L9(-51.18,-38.39) L10(-25.59,-38.39) L11(0,-38.39) L12(25.59,-38.39) L13(51.18,-38.39) L14(76.77,-38.39) L15(102.36,-38.39) L18(179.13,-38.39) L19(204.72,-38.39) L20(230.31,-38.39) L21(255.91,-38.39) M1(-255.91,-63.98) M2(-230.31,-63.98) M3(-204.72,-63.98) M18(179.13,-63.98) M19(204.72,-63.98) M20(230.31,-63.98) N2(-230.31,-89.57) N3(-204.72,-89.57) N4(-179.13,-89.57) N5(-153.54,-89.57) N6(-127.95,-89.57) N7(-102.36,-89.57) N9(-51.18,-89.57) N10(-25.59,-89.57) N12(25.59,-89.57) N13(51.18,-89.57) N15(102.36,-89.57) N16(127.95,-89.57) N18(179.13,-89.57) N19(204.72,-89.57) N20(230.31,-89.57) N21(255.91,-89.57) P1(-255.91,-115.16) P2(-230.31,-115.16) P3(-204.72,-115.16) P4(-179.13,-115.16) P5(-153.54,-115.16) P6(-127.95,-115.16) P7(-102.36,-115.16) P9(-51.18,-115.16) P10(-25.59,-115.16) P12(25.59,-115.16) P13(51.18,-115.16) P15(102.36,-115.16) P16(127.95,-115.16) P18(179.13,-115.16) P20(230.31,-115.16) P21(255.91,-115.16) R1(-255.91,-140.75) R2(-230.31,-140.75) R3(-204.72,-140.75) R4(-179.13,-140.75) R5(-153.54,-140.75) R6(-127.95,-140.75) R9(-51.18,-140.75) R12(25.59,-140.75) R15(102.36,-140.75) R18(179.13,-140.75) R19(204.72,-140.75) R20(230.31,-140.75) R21(255.91,-140.75) T1(-255.91,-166.34) T2(-230.31,-166.34) T3(-204.72,-166.34) T4(-179.13,-166.34) T5(-153.54,-166.34) T6(-127.95,-166.34) T7(-102.36,-166.34) T8(-76.77,-166.34) T9(-51.18,-166.34) T10(-25.59,-166.34) T11(0,-166.34) T12(25.59,-166.34) T14(76.77,-166.34) T15(102.36,-166.34) T16(127.95,-166.34) T17(153.54,-166.34) T18(179.13,-166.34) T20(230.31,-166.34) T21(255.91,-166.34) U1(-255.91,-191.93) U2(-230.31,-191.93) U3(-204.72,-191.93) U4(-179.13,-191.93) U5(-153.54,-191.93) U6(-127.95,-191.93) U8(-76.77,-191.93) U9(-51.18,-191.93) U10(-25.59,-191.93) U11(0,-191.93) U12(25.59,-191.93) U13(51.18,-191.93) U14(76.77,-191.93) U15(102.36,-191.93) U16(127.95,-191.93) U17(153.54,-191.93) U18(179.13,-191.93) U19(204.72,-191.93) U20(230.31,-191.93) U21(255.91,-191.93) V1(-255.91,-217.52) V2(-230.31,-217.52) V3(-204.72,-217.52) V5(-153.54,-217.52) V8(-76.77,-217.52) V10(-25.59,-217.52) V12(25.59,-217.52) V15(102.36,-217.52) V17(153.54,-217.52) V19(204.72,-217.52) V20(230.31,-217.52) V21(255.91,-217.52)
  silkscreen extent -278,-238 278,238, body extent -272,-234 272,234, height 56
C0201 [mil]
  rect 14.51x12.76 smd paste-3937.01 mask+2: 1(-10.8,0) 2(10.8,0)
  silkscreen extent -27,-15 27,15, body extent -12,-6 12,6, height 12
C0402 [mm]
  rect 0.79x0.54 smd paste-100 mask+0.051: 1(-0.545,0) 2(0.545,0)
  silkscreen extent -1.17,-0.5 1.17,0.5, body extent -0.5,-0.25 0.5,0.25, height 0.5
C0402-NSK [mil]
  rect 22x22 smd paste+0 mask+2: 1(-19.99,0) 2(20.01,0)
  silkscreen extent 0,-5 0,6, body extent -20,-10 20,10, height 20
"C0603 NSK" [mm]
  rect 0.85x0.85 smd paste+0 mask+0.051: 1(-0.75,0) 2(0.75,0)
  silkscreen extent 0,-0.21 0,0.21, body extent -0.8,-0.4 0.8,0.4, height 0.8
CONN-SMD_2P-P1.25_053398-0X71 [mil]
  rect 31.5x63 smd paste+0 mask+2: 1(-24.8,57.1) 2(24.8,57.1)
  rect 78.7x118.1 smd paste+0 mask+2: 3(127.2,-57.1) 4(-127.1,-57.1)
  silkscreen extent -145,-102 145,48, body extent -151,-97 151,64, height 185
CONN-SMD_6P-P1.25_53261-0671 [mil]
  rect 31.5x63 smd paste+0 mask+2: 1(123,57.1) 2(73.8,57.1) 3(24.6,57.1) 4(-24.6,57.1) 5(-73.8,57.1) 6(-123,57.1)
  rect 90.6x126 smd paste+0 mask+2: 7(-223.4,-57.1) 8(223.4,-57.1)
  silkscreen extent -241,-143 242,21, body extent -249,-143 249,61, height 134
D0402 [mil]
  rect 19.89x21.68 smd paste-3937.01 mask+2: 1(-16.4,0) 2(16.4,0)
  silkscreen extent -37,-9 -31,9, body extent -20,-10 20,10, height 14
FBGA96 [mil]
  round 14 smd: A1(-128.4,241.4) A2(-96.9,241.4) A3(-65.4,241.4) A7(60.6,241.4) A8(92.1,241.4) A9(123.6,241.4) B1(-128.4,209.9) B2(-96.9,209.9) B3(-65.4,209.9) B7(60.6,209.9) B8(92.1,209.9) B9(123.6,209.9) C1(-128.4,178.4) C2(-96.9,178.4) C3(-65.4,178.4) C7(60.6,178.4) C8(92.1,178.4) C9(123.6,178.4) D1(-128.4,146.9) D2(-96.9,146.9) D3(-65.4,146.9) D7(60.6,146.9) D8(92.1,146.9) D9(123.6,146.9) E1(-128.4,115.4) E2(-96.9,115.4) E3(-65.4,115.4) E7(60.6,115.4) E8(92.1,115.4) E9(123.6,115.4) F1(-128.4,83.9) F2(-96.9,83.9) F3(-65.4,83.9) F7(60.6,83.9) F8(92.1,83.9) F9(123.6,83.9) G1(-128.4,52.4) G2(-96.9,52.4) G3(-65.4,52.4) G7(60.6,52.4) G8(92.1,52.4) G9(123.6,52.4) H1(-128.4,20.9) H2(-96.9,20.9) H3(-65.4,20.9) H7(60.6,20.9) H8(92.1,20.9) H9(123.6,20.9) J1(-128.4,-10.6) J2(-96.9,-10.6) J3(-65.4,-10.6) J7(60.6,-10.6) J8(92.1,-10.6) J9(123.6,-10.6) K1(-128.4,-42.1) K2(-96.9,-42.1) K3(-65.4,-42.1) K7(60.6,-42.1) K8(92.1,-42.1) K9(123.6,-42.1) L1(-128.4,-73.6) L2(-96.9,-73.6) L3(-65.4,-73.6) L7(60.6,-73.6) L8(92.1,-73.6) L9(123.6,-73.6) M1(-128.4,-105.1) M2(-96.9,-105.1) M3(-65.4,-105.1) M7(60.6,-105.1) M8(92.1,-105.1) M9(123.6,-105.1) N1(-128.4,-136.6) N2(-96.9,-136.6) N3(-65.4,-136.6) N7(60.6,-136.6) N8(92.1,-136.6) N9(123.6,-136.6) P1(-128.4,-168.1) P2(-96.9,-168.1) P3(-65.4,-168.1) P7(60.6,-168.1) P8(92.1,-168.1) P9(123.6,-168.1) R1(-128.4,-199.6) R2(-96.9,-199.6) R3(-65.4,-199.6) R7(60.6,-199.6) R8(92.1,-199.6) R9(123.6,-199.6) T1(-128.4,-231.1) T2(-96.9,-231.1) T3(-65.4,-231.1) T7(60.6,-231.1) T8(92.1,-231.1) T9(123.6,-231.1)
  silkscreen extent -168,-255 149,275, body extent -186,-290 186,290, height 46
FBGA-153_L13.0-W11.5 [mm]
  oval 0.2x0.305 smd paste-100 mask+0.051: A1(-3.25,3.25) A2(-2.75,3.25) A3(-2.25,3.25) A4(-1.75,3.25) A5(-1.25,3.25) A6(-0.75,3.25) A7(-0.25,3.25) A8(0.25,3.25) A9(0.75,3.25) A10(1.25,3.25) A11(1.75,3.25) A12(2.25,3.25) A13(2.75,3.25) A14(3.25,3.25) P1(-3.25,-3.25) P2(-2.75,-3.25) P3(-2.25,-3.25) P4(-1.75,-3.25) P5(-1.25,-3.25) P6(-0.75,-3.25) P7(-0.25,-3.25) P8(0.25,-3.25) P9(0.75,-3.25) P10(1.25,-3.25) P11(1.75,-3.25) P12(2.25,-3.25) P13(2.75,-3.25) P14(3.25,-3.25)
  oval 0.305x0.2 smd paste-100 mask+0.051: B1(-3.25,2.75) B14(3.25,2.75) C1(-3.25,2.25) C14(3.25,2.25) D1(-3.25,1.75) D14(3.25,1.75) E1(-3.25,1.25) E14(3.25,1.25) F1(-3.25,0.75) F14(3.25,0.75) G1(-3.25,0.25) G14(3.25,0.25) H1(-3.25,-0.25) H14(3.25,-0.25) J1(-3.25,-0.75) J14(3.25,-0.75) K1(-3.25,-1.25) K14(3.25,-1.25) L1(-3.25,-1.75) L14(3.25,-1.75) M1(-3.25,-2.25) M14(3.25,-2.25) N1(-3.25,-2.75) N14(3.25,-2.75)
  round 0.25 smd paste-100 mask+0.051: B2(-2.75,2.75) B3(-2.25,2.75) B4(-1.75,2.75) B5(-1.25,2.75) B6(-0.75,2.75) B7(-0.25,2.75) B8(0.25,2.75) B9(0.75,2.75) B10(1.25,2.75) B11(1.75,2.75) B12(2.25,2.75) B13(2.75,2.75) C2(-2.75,2.25) C3(-2.25,2.25) C4(-1.75,2.25) C5(-1.25,2.25) C6(-0.75,2.25) C7(-0.25,2.25) C8(0.25,2.25) C9(0.75,2.25) C10(1.25,2.25) C11(1.75,2.25) C12(2.25,2.25) C13(2.75,2.25) D2(-2.75,1.75) D3(-2.25,1.75) D4(-1.75,1.75) D12(2.25,1.75) D13(2.75,1.75) E2(-2.75,1.25) E3(-2.25,1.25) E5(-1.25,1.25) E6(-0.75,1.25) E7(-0.25,1.25) E8(0.25,1.25) E9(0.75,1.25) E10(1.25,1.25) E12(2.25,1.25) E13(2.75,1.25) F2(-2.75,0.75) F3(-2.25,0.75) F5(-1.25,0.75) F10(1.25,0.75) F12(2.25,0.75) F13(2.75,0.75) G2(-2.75,0.25) G3(-2.25,0.25) G5(-1.25,0.25) G10(1.25,0.25) G12(2.25,0.25) G13(2.75,0.25) H2(-2.75,-0.25) H3(-2.25,-0.25) H5(-1.25,-0.25) H10(1.25,-0.25) H12(2.25,-0.25) H13(2.75,-0.25) J2(-2.75,-0.75) J3(-2.25,-0.75) J5(-1.25,-0.75) J10(1.25,-0.75) J12(2.25,-0.75) J13(2.75,-0.75) K2(-2.75,-1.25) K3(-2.25,-1.25) K5(-1.25,-1.25) K6(-0.75,-1.25) K7(-0.25,-1.25) K8(0.25,-1.25) K9(0.75,-1.25) K10(1.25,-1.25) K12(2.25,-1.25) K13(2.75,-1.25) L2(-2.75,-1.75) L3(-2.25,-1.75) L12(2.25,-1.75) L13(2.75,-1.75) M2(-2.75,-2.25) M3(-2.25,-2.25) M4(-1.75,-2.25) M5(-1.25,-2.25) M6(-0.75,-2.25) M7(-0.25,-2.25) M8(0.25,-2.25) M9(0.75,-2.25) M10(1.25,-2.25) M11(1.75,-2.25) M12(2.25,-2.25) M13(2.75,-2.25) N2(-2.75,-2.75) N3(-2.25,-2.75) N4(-1.75,-2.75) N5(-1.25,-2.75) N6(-0.75,-2.75) N7(-0.25,-2.75) N8(0.25,-2.75) N9(0.75,-2.75) N10(1.25,-2.75) N11(1.75,-2.75) N12(2.25,-2.75) N13(2.75,-2.75)
  silkscreen extent -5.84,-6.61 5.84,6.6, body extent -5.78,-6.54 5.79,6.54, height 0.92
HDMI-SMD_HDMI-019S [mm]
  oval 0.25x2.4 smd paste-100 mask+0.051: 1(4.501,3.396) 2(4.001,3.396) 3(3.501,3.396) 4(3.001,3.396) 5(2.5,3.396) 6(2,3.396) 7(1.5,3.396) 8(1,3.396) 9(0.5,3.396) 10(0,3.396) 11(-0.5,3.396) 12(-1,3.396) 13(-1.5,3.396) 14(-2,3.396) 15(-2.5,3.396) 16(-3.001,3.396) 17(-3.501,3.396) 18(-4.001,3.396) 19(-4.501,3.396)
  oval 1.5x2.7 hole 0.9 slot 2.1 at 90 deg copper offset -0.001,0.001 paste-2539.97 mask+0.051: 20(7.251,-3.397)
  oval 1.5x2.7 hole 0.9 slot 2.1 at 90 deg copper offset 0.001,0.001 paste-2539.97 mask+0.051: 21(-7.251,-3.397)
  oval 1.5x3.3 hole 0.9 slot 2.7 at 90 deg copper offset -0.001,0.001 paste-2539.97 mask+0.051: 22(7.251,2.563)
  oval 1.5x3.3 hole 0.9 slot 2.7 at 90 deg copper offset 0.001,0.001 paste-2539.97 mask+0.051: 23(-7.251,2.563)
  silkscreen extent -7.5,-8.04 7.5,3.56, body extent -7.5,-8.01 7.5,3.89, height 5.71
HDR-TH_40P-P2.54-V-M-R2-C20-S2.54 [mm]
  rect 1.575x1.8 hole 1.1: 1(-24.13,-1.27)
  round 1.8 hole 1.1: 2(-24.13,1.27) 3(-21.59,-1.27) 4(-21.59,1.27) 5(-19.05,-1.27) 6(-19.05,1.27) 7(-16.51,-1.27) 8(-16.51,1.27) 9(-13.97,-1.27) 10(-13.97,1.27) 11(-11.43,-1.27) 12(-11.43,1.27) 13(-8.89,-1.27) 14(-8.89,1.27) 15(-6.35,-1.27) 16(-6.35,1.27) 17(-3.81,-1.27) 18(-3.81,1.27) 19(-1.27,-1.27) 20(-1.27,1.27) 21(1.27,-1.27) 22(1.27,1.27) 23(3.81,-1.27) 24(3.81,1.27) 25(6.35,-1.27) 26(6.35,1.27) 27(8.89,-1.27) 28(8.89,1.27) 29(11.43,-1.27) 30(11.43,1.27) 31(13.97,-1.27) 32(13.97,1.27) 33(16.51,-1.27) 34(16.51,1.27) 35(19.05,-1.27) 36(19.05,1.27) 37(21.59,-1.27) 38(21.59,1.27) 39(24.13,-1.27) 40(24.13,1.27)
  silkscreen extent -25.4,-2.54 25.4,2.54, body extent -25.4,-2.5 25.41,2.5, height 8.54
IND-SMD_L2.0-W1.6_1 [mm]
  rect 1x1.72 smd paste+0 mask+0.051: 1(0.828,0) 2(-0.828,0)
  silkscreen extent -1.14,-1.02 1.14,1.02, body extent -1.01,-0.8 1.01,0.8, height 1.12
IPEX-SMD_BWIPX-1-001E [mm]
  rect 1.05x1 smd: 1(-0.763,0)
  rect 2.2x1.05 smd: 2(0.763,-1.475) 3(0.763,1.475)
  silkscreen extent -0.64,-1.27 2.16,1.27, body extent -0.79,-1.5 2.31,1.5, height 1.26
KEY-SMD_4P-L4.2-W3.2-P2.20-LS4.6 [mm]
  rect 1.05x0.7 smd: 1(-2.1,1.075) 2(2.1,1.075) 3(-2.1,-1.075) 4(2.1,-1.075)
  silkscreen extent -2.2,-1.55 2.2,1.52, body extent -2.35,-1.6 2.35,1.6, height 2.51
L0201 [mil]
  rect 14.51x12.76 smd paste-3937.01 mask+2: 1(-10.8,0) 2(10.8,0)
  silkscreen extent -27,-15 27,15, body extent -12,-6 12,6, height 12
L0201-RD [mil]
  rect 14.51x12.76 smd paste-3937.01 mask+2: 1(-10.8,0) 2(10.8,0)
  silkscreen extent -35,-15 27,15
L0402 [mm]
  rect 0.79x0.54 smd paste-100 mask+0.051: 1(-0.545,0) 2(0.545,0)
  silkscreen extent -1.17,-0.5 1.17,0.5, body extent -0.5,-0.25 0.5,0.25, height 0.5
LED0402-R-RD_RED [mm]
  rect 0.75x0.6 smd: 1(0.623,0) 2(-0.623,0)
  silkscreen extent -1.51,-0.61 1.26,0.58, body extent -0.51,-0.25 0.51,0.26, height 0.41
OSC-SMD_4P-L2.0-W1.6-BL [mil]
  rect 30x20 smd: 1(-25,-20) 2(25,-20) 3(25,20) 4(-25,20)
  body extent -63,-49 63,49, height 32
osc-smd_4p-l2.0-w1.6-bl [mil]
  rect 30x20 smd: 1(-25,-20) 2(25,-20) 3(25,20) 4(-25,20)
  body extent -63,-49 63,49, height 32
QFN-32_L5.0-W5.0-P0.50-TL-EP3.5 [mm]
  oval 0.8x0.28 smd paste-100 mask+0.051: 1(-2.5,1.75) 2(-2.5,1.25) 3(-2.5,0.75) 4(-2.5,0.25) 5(-2.5,-0.25) 6(-2.5,-0.75) 7(-2.5,-1.25) 8(-2.5,-1.75) 17(2.5,-1.75) 18(2.5,-1.25) 19(2.5,-0.75) 20(2.5,-0.25) 21(2.5,0.25) 22(2.5,0.75) 23(2.5,1.25) 24(2.5,1.75)
  oval 0.28x0.8 smd paste-100 mask+0.051: 9(-1.75,-2.5) 10(-1.25,-2.5) 11(-0.75,-2.5) 12(-0.25,-2.5) 13(0.25,-2.5) 14(0.75,-2.5) 15(1.25,-2.5) 16(1.75,-2.5) 25(1.75,2.5) 26(1.25,2.5) 27(0.75,2.5) 28(0.25,2.5) 29(-0.25,2.5) 30(-0.75,2.5) 31(-1.25,2.5) 32(-1.75,2.5)
  rect 3.5x3.5 smd paste-100 mask+0.051: 33(0,0)
  silkscreen extent -3.18,-2.6 2.6,2.6, body extent -2.5,-2.5 2.5,2.5, height 1.03
R0402 [mm]
  rect 0.566x0.54 smd paste-100 mask+0.051: 1(-0.433,0) 2(0.433,0)
  silkscreen extent -0.94,-0.5 0.94,0.5, body extent -0.5,-0.25 0.5,0.25, height 0.5
R0402-NSK_2 [mil]
  rect 19.68x22 smd paste+0 mask+2: 1(-18,0) 2(18,0)
  body extent -20,-10 20,10, height 14
R0603 [mil]
  rect 31.75x34.02 smd paste-3937.01 mask+2: 1(-29.66,0) 2(29.66,0)
  silkscreen extent -55,-26 55,26, body extent -32,-16 32,16, height 18
SIM-SMD_8P-1040310811 [mm]
  rect 0.7x1.2 smd paste+0 mask+0.051: 1(3.138,-5.337) 2(2.037,-5.337) 3(0.938,-5.337) 4(-0.162,-5.337) 5(-1.263,-5.337) 6(-2.363,-5.337) 7(-3.462,-5.337) 8(-4.562,-5.337)
  rect 1.17x1.8 smd paste+0 mask+0.051: 9(-5.773,-5.138)
  rect 1.55x1.35 smd paste+0 mask+0.051: 10(5.598,-5.313)
  rect 1.2x1 smd paste+0 mask+0.051: 11(5.773,0.663) 12(5.773,4.363)
  rect 1.9x1.35 smd paste+0 mask+0.051: 13(2.273,5.337) 14(-3.697,5.337)
  silkscreen extent -6.07,-5.64 5.99,5.67, body extent -5.97,-5.75 5.97,5.65, height 1.47
SLP2510P8_L2.5-W1.0-P0.50-BL [mil]
  rect 7.9x26.8 smd paste+0 mask+2: 1(-39.4,-17.3) 2(-19.7,-17.3) 4(19.7,-17.3) 5(39.4,-17.3) 6(39.4,17.3) 7(19.7,17.3) 9(-19.7,17.3) 10(-39.4,17.3)
  rect 15.7x26.8 smd paste+0 mask+2: 3(0,-17.3) 8(0,17.3)
  silkscreen extent -57,-35 51,22, body extent -48,-20 48,20, height 22
SOD-323_L1.8-W1.3-LS2.5-NSK [mil]
  rect 33.3x17.9 smd paste+0 mask+2: 1(-43.2,0) 2(43.2,0)
  silkscreen extent -18,-10 -6,7, body extent -48,-26 50,26, height 47
SOD-523_L1.2-W0.8-LS1.6-FD [mil]
  rect 23.6x23.6 smd paste+0 mask+2: 1(-31.5,0) 2(31.5,0)
  silkscreen extent -26,-18 26,18, body extent -32,-16 32,16, height 28
USB-C-SMD_TYPEC-304-BCP16-1 [mil]
  oval 39.4x82.7 hole 23.6 slot 66.9 at 90 deg paste-99999 mask+1.97: 12(-170.1,64.3) 13(170.1,64.3)
  oval 39.4x63 hole 23.6 slot 47.2 at 90 deg paste-99999 mask+1.97: 14(-170.1,-100.3) 15(170.1,-100.3)
  rect 21.7x57.1 smd paste-3937.01 mask+1.97: A1B12(-127,100.3) A4B9(-96.5,100.3) B1A12(127,100.3) B4A9(96.5,100.3)
  rect 11.8x57.1 smd paste-3937.01 mask+1.97: A5(-49.2,100.3) A6(-9.8,100.3) A7(9.8,100.3) A8(49.2,100.3) B5(68.9,100.3) B6(29.5,100.3) B7(-29.5,100.3) B8(-68.9,100.3)
  Keep-Out Layer board cut-out: -101,43.4 -101,45.95 -102.95,50.65 -106.55,54.25 -111.25,56.2 -116.35,56.2 -121.05,54.25 -124.65,50.65 -126.6,45.95 -126.6,43.4 -126.6,40.85 -124.65,36.15 -121.05,32.55 -116.35,30.6 -111.25,30.6 -106.55,32.55 -102.95,36.15 -101,40.85 -101,43.4
  Keep-Out Layer board cut-out: 126.6,43.4 126.6,45.95 124.65,50.65 121.05,54.25 116.35,56.2 111.25,56.2 106.55,54.25 102.95,50.65 101,45.95 101,43.4 101,40.85 102.95,36.15 106.55,32.55 111.25,30.6 116.35,30.6 121.05,32.55 124.65,36.15 126.6,40.85 126.6,43.4
  Keep-Out Layer circle w0.2: c-113.8,43.4 r12.8
  Keep-Out Layer circle w10: c-113.8,43.4 r12.8
  Keep-Out Layer circle w0.2: c113.8,43.4 r12.8
  Keep-Out Layer circle w10: c113.8,43.4 r12.8
  silkscreen extent -173,-203 173,16, body extent -176,-200 176,106, height 127
WQFN-20_L3.0-W3.0-P0.40-BL-EP [mil]
  rect 7.9x31.5 smd paste+0 mask+2: 1(-31.5,-59.1) 2(-15.8,-59.1) 3(0,-59.1) 4(15.7,-59.1) 5(31.5,-59.1) 11(31.5,59.1) 12(15.7,59.1) 13(0,59.1) 14(-15.8,59.1) 15(-31.5,59.1)
  rect 31.5x7.9 smd paste+0 mask+2: 6(59.1,-31.5) 7(59.1,-15.7) 8(59.1,0) 9(59.1,15.7) 10(59.1,31.5) 16(-59.1,31.5) 17(-59.1,15.8) 18(-59.1,0) 19(-59.1,-15.7) 20(-59.1,-31.5)
  rect 66.9x66.9 smd paste+0 mask+2: 21(0,0)
  silkscreen extent -61,-83 61,61, body extent -59,-59 59,59, height 33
